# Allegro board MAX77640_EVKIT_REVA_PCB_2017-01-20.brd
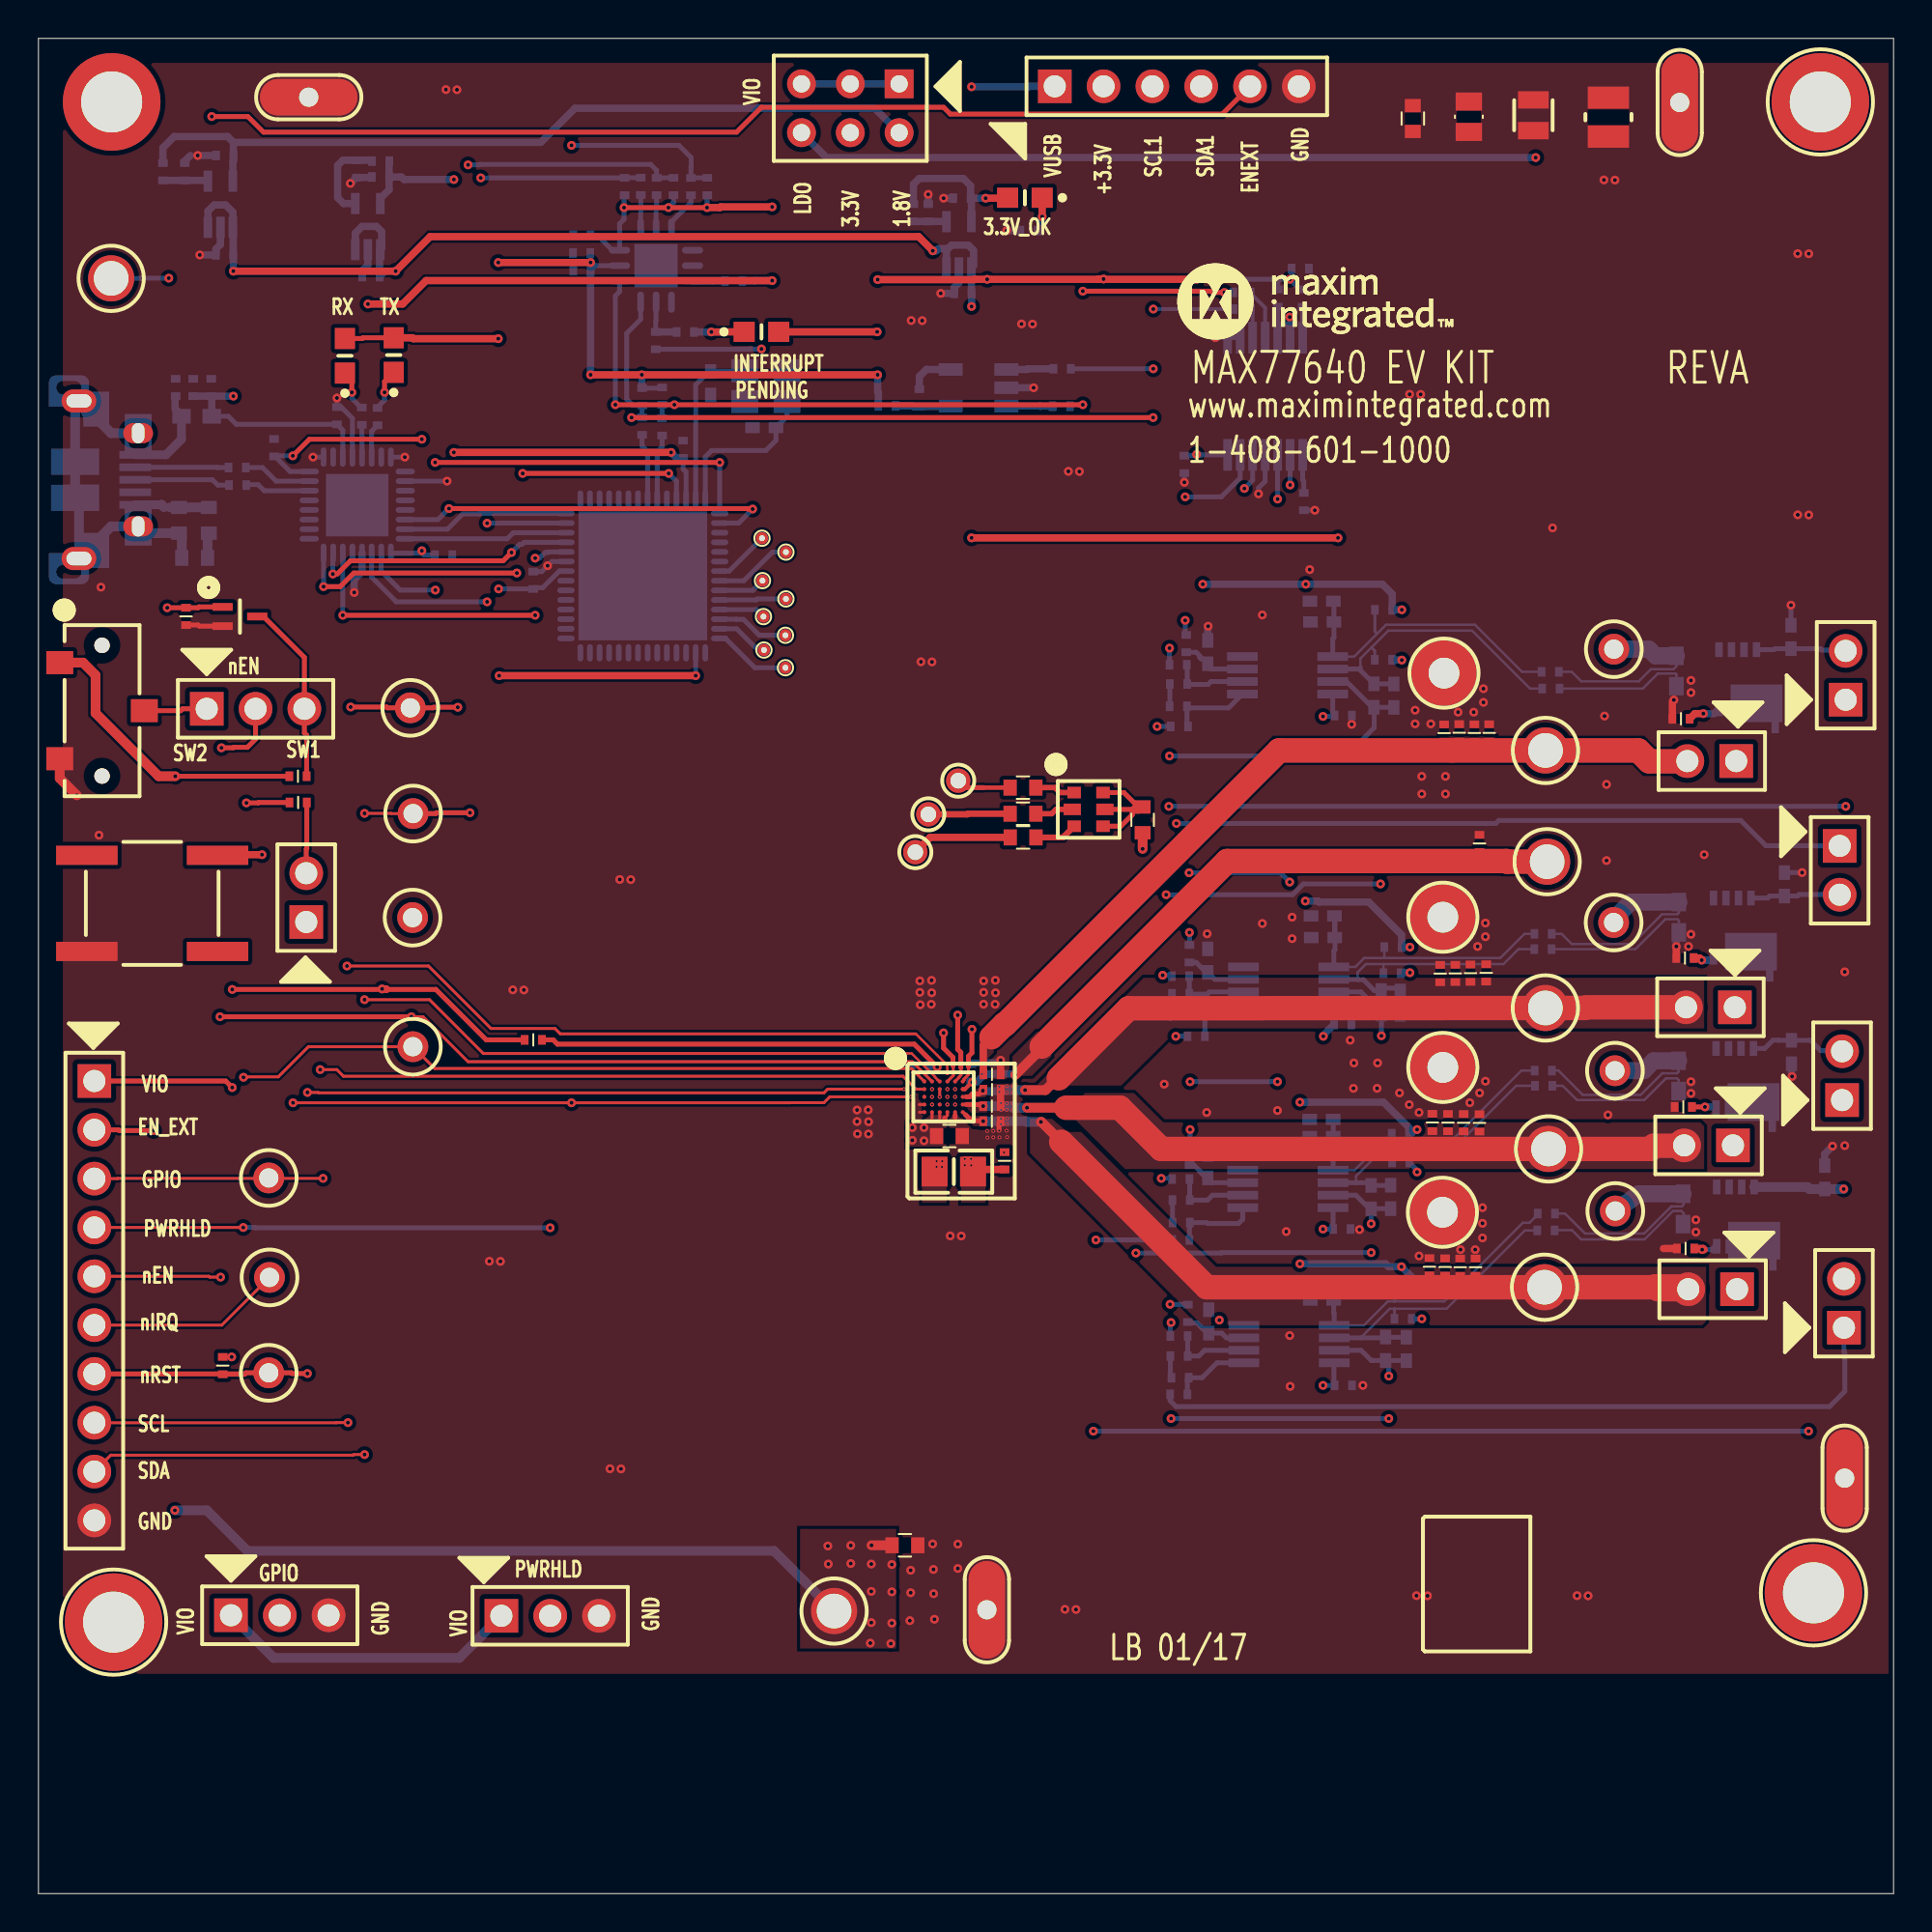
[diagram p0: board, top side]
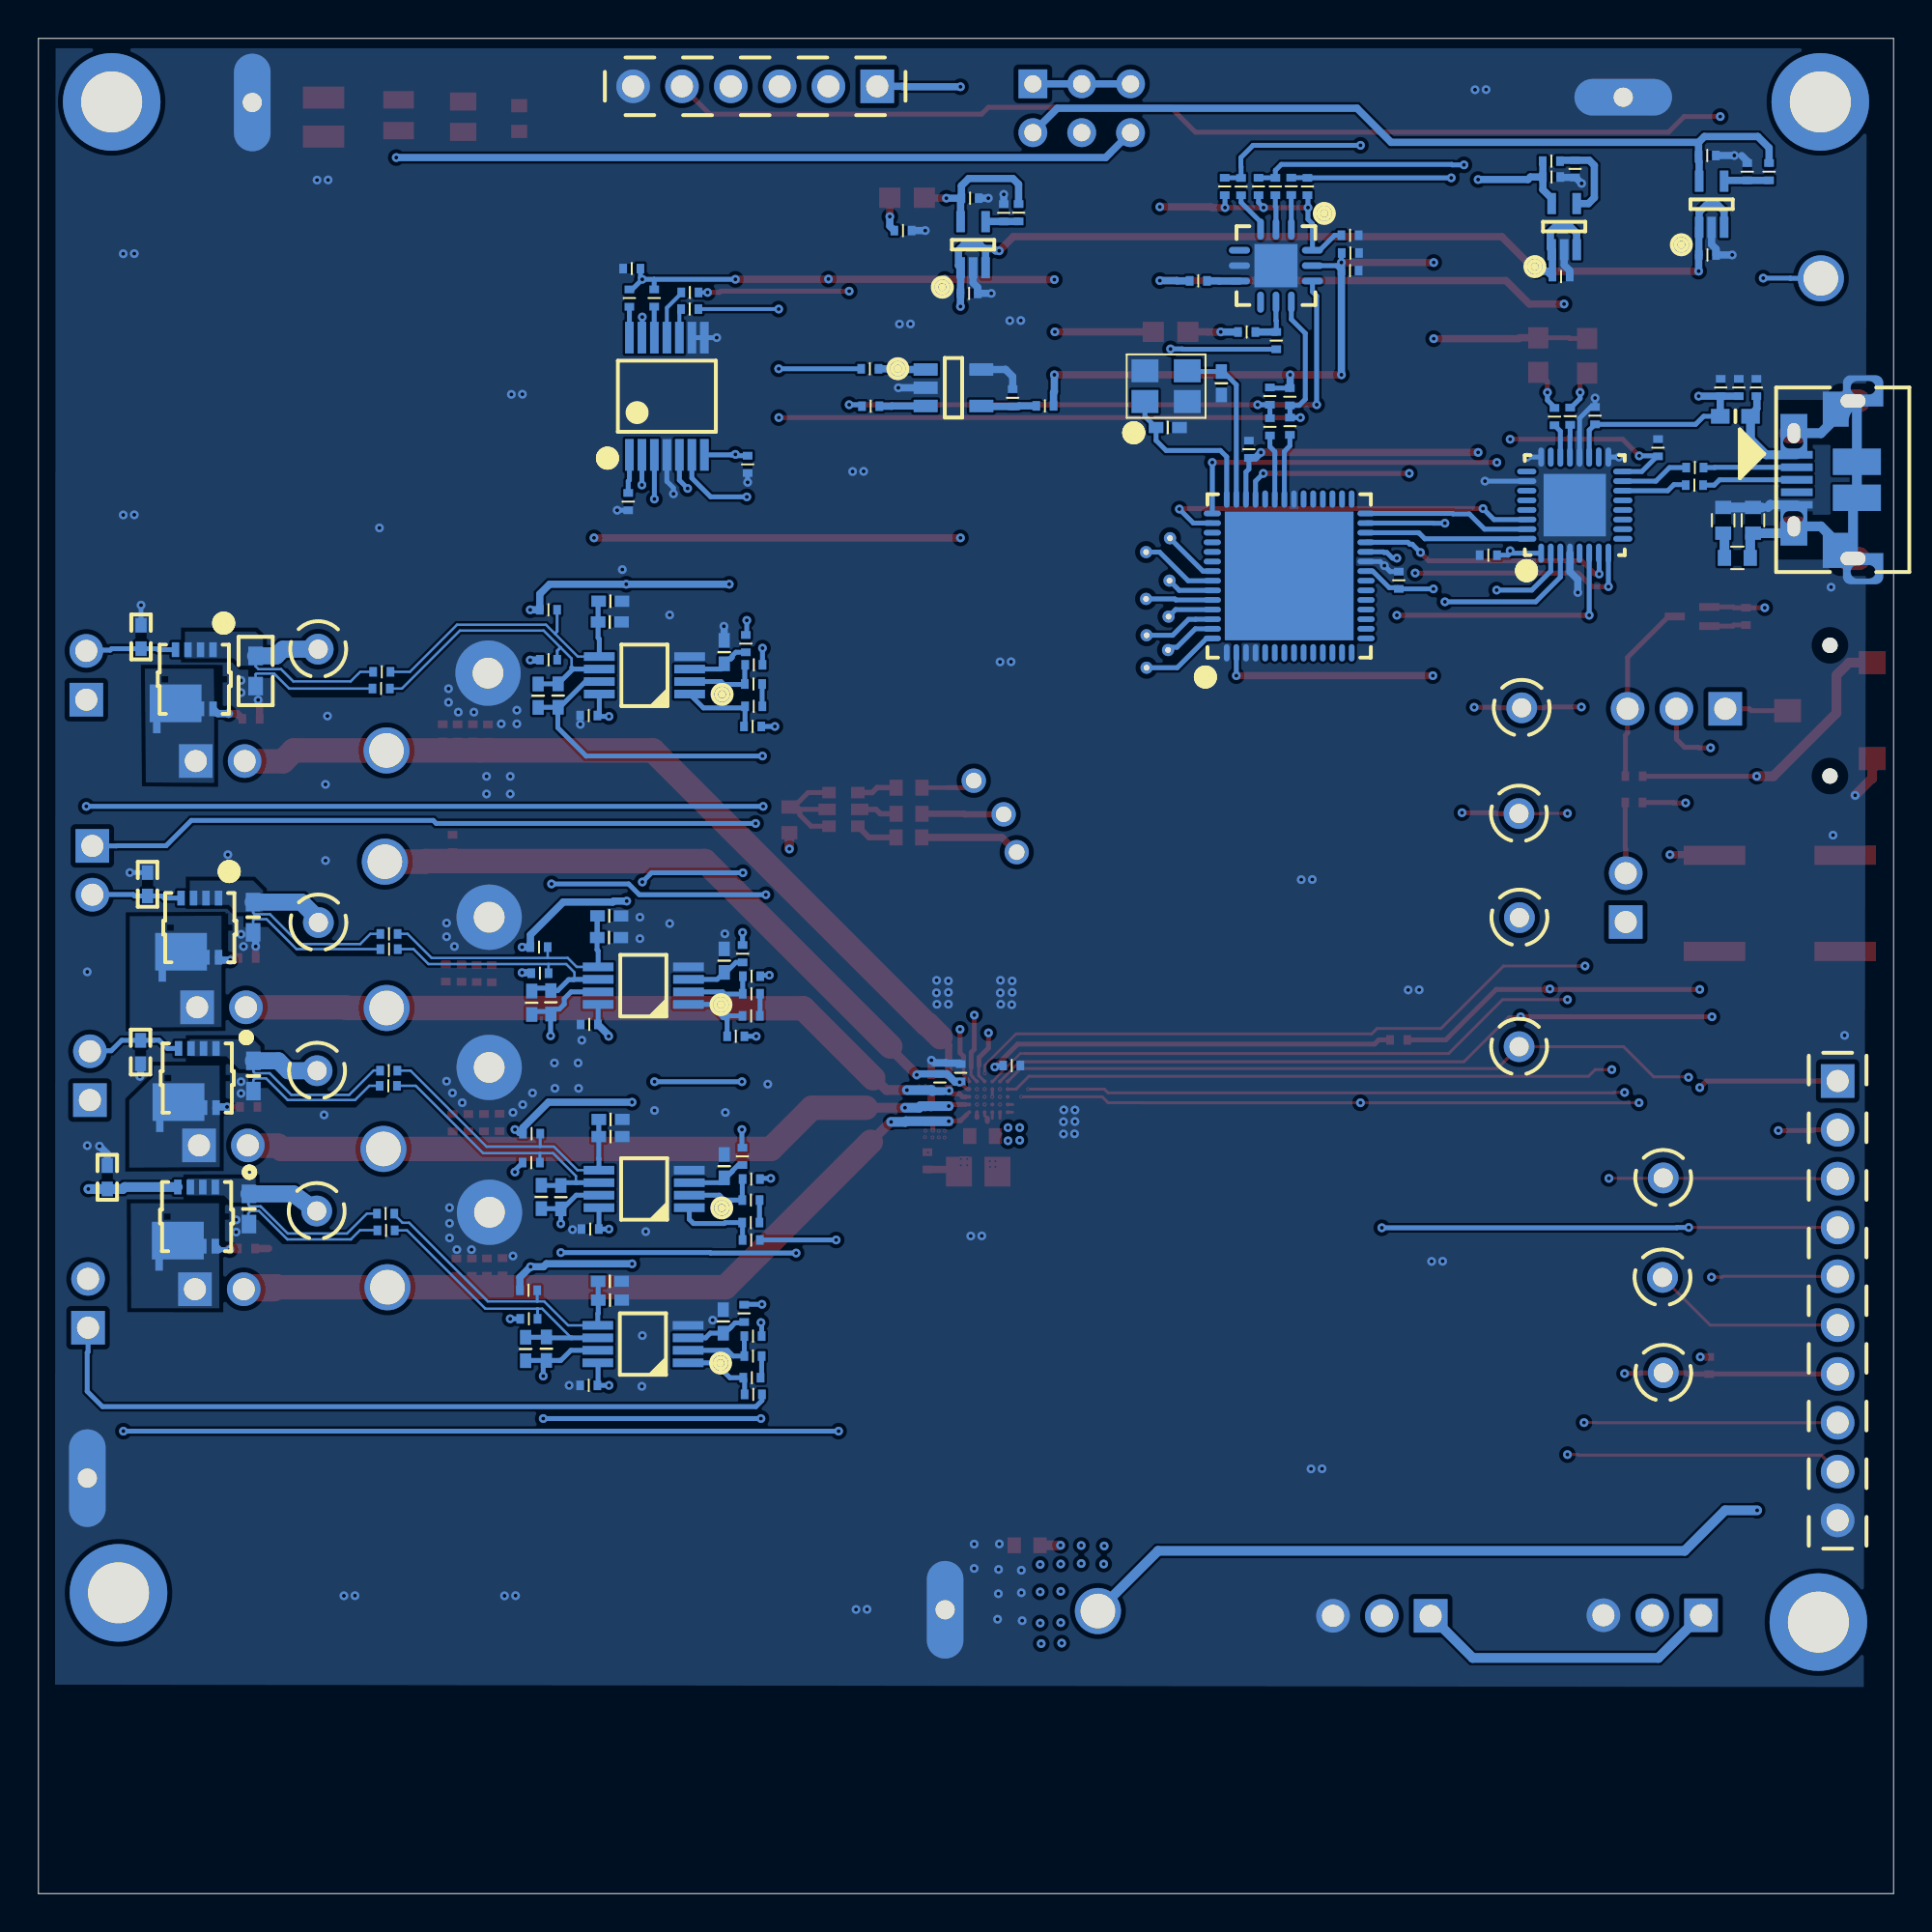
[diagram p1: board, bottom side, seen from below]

Outline 96.52 x 96.52 mm; copper layers: TOP, INTERNAL2, INTERNAL3, BOTTOM. Coordinates in mm from the lower left corner of the outline.
Outline path: 0,96.52 0,0 96.52,0 96.52,96.52 0,96.52

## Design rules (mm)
constraint set DEFAULT: min track width 0.102
net group NIRQ: nets NIRQ UNNAMED_4_EKRESSMD_I87_1
net group NIRQ1: nets NIRQ1 UNNAMED_4_EKRESSMD_I190_2
net group UNNAMED_4_10103592-0001LF_I2_2: nets UNNAMED_4_10103592-0001LF_I2_2 UNNAMED_4_EKRESSMD_I15_2
net group UNNAMED_4_10103592-0001LF_I2_3: nets UNNAMED_4_10103592-0001LF_I2_3 UNNAMED_4_EKRESSMD_I16_2
net group UNNAMED_4_10103592-0001LF_I2_SHIELD10: nets UNNAMED_4_10103592-0001LF_I2_SHIELD10 UNNAMED_4_EKCAPNP_I29_1
net group UNNAMED_4_EKRESSMD_I17_1: nets UNNAMED_4_EKRESSMD_I17_1 UNNAMED_4_EKRESSMD_I17_2
net group UNNAMED_4_EKRESSMD_I18_1: nets UNNAMED_4_EKRESSMD_I18_1 UNNAMED_4_EKRESSMD_I18_2
net group VUSB: nets UNNAMED_4_10103592-0001LF_I2_1 VUSB
net group SCL: nets SCL SDA UNNAMED_4_EKRESSMD_I153_1 UNNAMED_4_EKRESSMD_I154_1 UNNAMED_4_EKRESSMD_I171_2 VIO
net group SCL1: nets SCL1 UNNAMED_4_EKRESSMD_I109_1 UNNAMED_6_24AA02_I452_SCL
net group SDA1: nets SDA1 UNNAMED_4_EKRESSMD_I113_1 UNNAMED_6_24AA02_I452_SDA

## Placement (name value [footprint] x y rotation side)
C1  22UF  [CAPC1608X90L]  47.4 39.41 0 top
C2  0.01UF  [CAPC1005X50L]  75.33 47.9 270 top
C4  3300PF  [0402]  50.27 38.13 270 top
C5  10UF  [CAPC1005X50L]  49.61 42.62 180 top
C6  10UF  [CAPC1005X50L]  49.61 40.18 180 top
C8  10UF  [CAPC1005X50L]  49.61 40.97 180 top
C9  10UF  [CAPC1005X50L]  49.61 41.82 180 top
C12  1UF  [CAPC1005X50L]  45.88 43.08 0 bottom
C13  10UF  [CAPC1005X50L]  48.54 42.7 90 bottom
C14  0.1UF  [CAPC1005X50L]  45.83 77.82 270 bottom
C17  10UF  [CAPC1005X50L]  73.13 60.38 270 top
C18  OPEN  [CAPC1005X50L]  74.97 54.64 270 top
C19  OPEN  [CAPC1005X50L]  72.93 47.87 270 top
C20  10UF  [CAPC1005X50L]  72.53 40.12 270 top
C21  OPEN  [CAPC1005X50L]  73.72 47.88 270 top
C22  OPEN  [CAPC1005X50L]  73.34 40.11 270 top
C23  OPEN  [CAPC1005X50L]  73.92 60.39 270 top
C24  OPEN  [CAPC1005X50L]  72.37 32.61 270 top
C25  0.1UF  [CAPC1005X50L]  74.71 60.38 270 top
C26  OPEN  [CAPC1005X50L]  73.19 32.6 270 top
C27  0.1UF  [CAPC1005X50L]  74.51 47.89 270 top
C28  0.1UF  [CAPC1005X50L]  74.15 40.1 270 top
C29  0.1UF  [CAPC1005X50L]  73.97 32.59 270 top
C30  22UF  [CAPC1608X90L]  45.08 18.12 0 top
C31  0.01UF  [CAPC1005X50L]  74.97 40.1 270 top
C32  0.01UF  [CAPC1005X50L]  74.77 32.59 270 top
C33  0.01UF  [CAPC1005X50L]  75.48 60.39 270 top
C108  0.1UF  [CAPC1005X50L]  15.53 76.89 270 bottom
C110  1UF  [CAPC1005X50L]  9.68 85.26 0 bottom
C111  1UF  [CAPC1005X50L]  9.69 90.43 0 bottom
C112  1UF  [CAPC1005X50L]  17.3 84.13 0 bottom
C113  1UF  [CAPC1005X50L]  17.8 89.31 0 bottom
C114  0.47UF  [CAPC1608X90L]  8.86 71.45 90 bottom
C115  1UF  [CAPC1005X50L]  28.28 84.44 0 bottom
C118  1UF  [CAPC1005X50L]  48.1 83.26 0 bottom
C120  1UF  [CAPC1005X50L]  28.28 86.28 0 bottom
C150  0.1UF  [CAPC1005X50L]  25.74 68.33 90 bottom
C151  0.1UF  [CAPC1005X50L]  33.54 75.15 90 bottom
C152  15PF  [0402#2]  37.76 76.28 0 bottom
C153  15PF  [0402#2]  34.97 78.58 90 bottom
C154  4.7UF  [CAPC1005X50L]  8.05 78.36 270 bottom
C155  0.1UF  [CAPC1005X50L]  7.14 78.36 90 bottom
C156  0.1UF  [CAPC1005X50L]  12.26 75.23 270 bottom
C157  0.1UF  [CAPC1005X50L]  28.26 85.36 0 bottom
C158  1UF  [CAPC1005X50L]  48.05 88.21 0 bottom
C159  0.1UF  [CAPC1005X50L]  21.08 69.63 0 bottom
C200  4700PF  [0402#2]  60.84 48.54 270 bottom
C201  1000PF  [CAPC1005X50L]  59.43 46.82 180 bottom
C202  0.1UF  [CAPC1005X50L]  67.86 45.22 0 bottom
C203  18PF  [0402#2]  69.86 46.37 90 bottom
C204  18PF  [0402#2]  66.83 49.74 0 bottom
C206  1000PF  [CAPC1005X50L]  59.45 36.08 180 bottom
C207  0.1UF  [CAPC1005X50L]  67.81 34.57 0 bottom
C208  18PF  [0402#2]  66.76 39.38 0 bottom
C209  18PF  [0402#2]  70.35 36.25 90 bottom
C211  1000PF  [CAPC1005X50L]  59.34 27.97 180 bottom
C212  0.1UF  [CAPC1005X50L]  67.89 26.44 0 bottom
C213  18PF  [0402#2]  70.09 28.35 90 bottom
C214  18PF  [0402#2]  66.78 30.88 0 bottom
C216  1000PF  [CAPC1005X50L]  59.32 62.93 180 bottom
C217  0.1UF  [CAPC1005X50L]  67.89 61.29 0 bottom
C218  18PF  [0402#2]  66.79 66.16 0 bottom
C219  18PF  [0402#2]  69.48 62.33 90 bottom
C221  0.1UF  [CAPC1005X50L]  65.65 84.55 180 bottom
C222  0.1UF  [CAPC1005X50L]  59.62 74.36 90 bottom
C223  0.1UF  [CAPC1005X50L]  65.83 72.42 90 bottom
C239  1UF  [CAPC1005X50L]  85.67 48.67 0 top
C240  1UF  [CAPC1005X50L]  85.58 40.93 0 top
C241  1UF  [CAPC1005X50L]  85.7 33.56 0 top
C242  1UF  [CAPC1005X50L]  85.46 61.12 0 top
C248  4700PF  [0402#2]  60.84 37.85 270 bottom
C250  4700PF  [0402#2]  60.89 29.77 270 bottom
C251  4700PF  [0402#2]  60.84 64.59 270 bottom
D100  LTST-C190YKT  [LEDC1608X80M]  18.48 80.05 90 top
D101  LTST-C190YKT  [LEDC1608X80M]  15.94 80.01 90 top
D102  LTST-C190CKT  [LEDC1608X80M]  51.32 88.23 180 top
D103  LTST-C190CKT  [LEDC1608X80M]  37.62 81.25 0 top
DS1  19-337/R6GHBHC-A01/2T  [LED_R6GHBHC]  54.64 56.41 0 top
EN_EXT  N/A  [TP_C240H180]  3.78 84.04 0 top
FB100  220  [0603#2]  8.23 76.86 0 bottom
GND1  N/A  [TP_C340H160]  73.13 63.5 90 top
GND2  MAXIMPAD  [EVK_MAXIMPAD]  49.35 14.77 270 top
GND3  MAXIMPAD  [EVK_MAXIMPAD]  14.06 93.46 0 top
GND4  MAXIMPAD  [EVK_MAXIMPAD]  85.39 93.19 270 top
GND5  N/A  [TP_C340H160]  73.05 35.45 0 top
GND6  N/A  [TP_C340H160]  73.07 42.98 0 top
GND7  N/A  [TP_C340H160]  73.07 50.8 0 top
GND8  MAXIMPAD  [EVK_MAXIMPAD]  93.98 21.61 90 top
GPIO  N/A  [TP_180P120D460H]  11.98 37.23 0 top
INLDO  N/A  [TP_C240H180]  78.5 53.69 0 top
J2  PBC10SAAN  [SULLINS_PXC10SAAN]  2.91 42.28 270 top
J3  TSW-103-07-T-S  [SAMTEC_TSW-103-07-T-S]  10.02 14.48 0 top
J4  TSW-103-07-T-S  [SAMTEC_TSW-103-07-T-S]  24.09 14.45 0 top
J5  TSW-103-07-T-S  [SAMTEC_TSW-103-07-T-S]  8.76 61.64 0 top
J6  10103592-0001LF  [FCI_10103592-0001LF]  2.11 73.56 90 bottom
J8  TSW-102-07-T-S  [SAMTEC_TSW-102-07-X-S]  13.93 50.55 90 top
J100  PBC06SAAN  [SULLINS_PXC06SAAN]  52.88 94.03 0 top
J101  TSW-102-26-T-T  [SAMTEC_TSW-102-26-X-T]  44.78 94.16 270 top
J200  TSW-102-07-T-S  [SAMTEC_TSW-102-07-X-S]  93.72 54.51 270 top
J201  TSW-102-07-T-S  [SAMTEC_TSW-102-07-X-S]  88.26 46.11 180 top
J202  TSW-102-07-T-S  [SAMTEC_TSW-102-07-X-S]  93.84 41.28 90 top
J203  TSW-102-07-T-S  [SAMTEC_TSW-102-07-X-S]  88.16 38.93 180 top
J204  TSW-102-07-T-S  [SAMTEC_TSW-102-07-X-S]  93.94 29.44 90 top
J205  TSW-102-07-T-S  [SAMTEC_TSW-102-07-X-S]  88.38 31.44 180 top
J206  TSW-102-07-T-S  [SAMTEC_TSW-102-07-X-S]  94.03 62.12 90 top
J207  TSW-102-07-T-S  [SAMTEC_TSW-102-07-X-S]  88.33 58.92 180 top
L1  1.5UH  [0805]  47.62 37.56 180 top
L2  0.47UH  [0603]  71.51 92.35 90 top
L3  2.2UH  [0805#2]  74.42 92.45 90 top
L4  2.2UH  [IND_2016]  77.78 92.53 90 top
L5  2.2UH  [IND_2520]  81.69 92.43 90 top
LDO  N/A  [TP_C240H180]  78.41 59.48 0 top
LED0  NA  [TP_C127H81]  47.86 57.9 0 top
LED1  NA  [TP_C127H81]  46.3 56.15 0 top
LED2  NA  [TP_C127H81]  45.62 54.18 0 top
NEN  N/A  [TP_180P120D460H]  19.47 50.78 0 top
NIRQ  N/A  [TP_180P120D460H]  12.02 32.06 0 top
NOREF  -  [unnamed]  3.91 14.12 0 top
NOREF#2  -  [unnamed]  3.81 93.22 0 top
NOREF#3  -  [unnamed]  92.35 15.65 0 top
NOREF#4  -  [#2]  61.29 82.75 0 top
NOREF#5  -  [#2]  -23.98 89.1 0 top
NOREF#6  -  [#2]  49.43 150.22 0 top
NOREF#7  -  [#2]  12.75 1.73 0 top
NOREF#8  -  [unnamed]  92.71 93.22 0 top
NOREF#9  -  [#2]  108.1 89.1 0 top
NOREF#10  -  [#2]  108.1 -9.96 0 top
NRST  N/A  [TP_180P120D460H]  11.98 27.09 0 top
PO0  N/A  [TP_C25H12]  37.65 70.52 90 top
PO1  N/A  [TP_C25H12]  38.89 69.8 90 top
PO2  N/A  [TP_C25H12]  37.67 68.31 90 top
PO3  N/A  [TP_C25H12]  38.89 67.36 90 top
PO4  N/A  [TP_C25H12]  37.72 66.44 90 top
PO5  N/A  [TP_C25H12]  38.86 65.47 90 top
PO6  N/A  [TP_C25H12]  37.75 64.7 90 top
PO7  N/A  [TP_C25H12]  38.86 63.78 90 top
PWRHLD  N/A  [TP_180P120D460H]  19.48 44.06 0 top
Q1  FDY300NZ  [SOT50P160X90-3M]  10.48 66.44 0 top
Q200  IRFHM8337TRPBF  [TRAN_IRF_PQFN8_SINGLE_B]  88.13 50.26 270 bottom
Q201  IRFHM8337TRPBF  [TRAN_IRF_PQFN8_SINGLE_B]  88.26 42.43 270 bottom
Q202  IRFHM8337TRPBF  [TRAN_IRF_PQFN8_SINGLE_B]  88.29 35.22 270 bottom
Q203  IRFHM8337TRPBF  [TRAN_IRF_PQFN8_SINGLE_B]  88.41 63.18 270 bottom
R1  100K  [RESC1005X50L]  7.61 89.59 90 bottom
R2  10K  [0402]  13.5 58.13 180 top
R3  100K  [RESC1005X50L]  7.68 66.45 270 top
R6  0  [RESC1608X90L]  51.23 54.95 180 top
R7  0  [RESC1608X90L]  51.22 57.54 180 top
R8  0  [RESC1608X90L]  51.22 56.18 180 top
R9  0  [RESC1608X90L]  57.45 55.86 90 top
R10  10K  [0402]  9.59 27.47 90 top
R11  0  [RESC1005X50L]  49.62 42.2 270 bottom
R14  100K  [RESC1005X50L]  34.8 88.82 270 bottom
R16  150  [0402]  13.51 56.77 0 top
R17  0  [RESC1005X50L]  25.75 44.42 180 top
R100  4.7K  [RESC1005X50L]  32.45 77.91 90 bottom
R103  22  [RESC1005X50L]  10.36 73.28 0 bottom
R107  2.2K  [RESC1005X50L]  33.04 88.82 90 bottom
R108  2.2K  [RESC1005X50L]  30.5 88.82 90 bottom
R109  100  [RESC1005X50L]  16.83 76.87 90 bottom
R110  470  [0402]  51.54 86.52 180 bottom
R111  100  [RESC1005X50L]  17.64 76.84 90 bottom
R115  100K  [RESC1005X50L]  8.99 78.36 90 bottom
R118  4.7K  [RESC1005X50L]  31.41 77.88 90 bottom
R122  1M  [RESC1608X90L]  7.32 71.45 90 bottom
R123  22  [RESC1005X50L]  10.34 74.19 0 bottom
R135  0  [RESC1005X50L]  31.34 88.83 90 bottom
R136  0  [RESC1005X50L]  32.16 88.82 90 bottom
R142  0  [RESC1608X90L]  8.13 69.49 0 bottom
R143  0  [RESC1005X50L]  36.17 83.91 180 bottom
R148  0  [RESC1005X50L]  32.45 76.31 90 bottom
R150  22  [RESC1005X50L]  33.95 88.81 90 bottom
R152  0  [RESC1005X50L]  32.12 80.8 90 bottom
R155  0  [RESC1005X50L]  31.41 76.34 90 bottom
R156  105K  [0402]  17.81 90.14 180 bottom
R157  100K  [RESC1005X50L]  16.57 89.73 270 bottom
R158  169K  [0402]  45.53 87.45 270 bottom
R159  100K  [RESC1005X50L]  46.29 87.45 90 bottom
R160  47.5K  [0402]  6.48 89.59 270 bottom
R161  470  [0402]  33.66 81.25 180 bottom
R162  0  [RESC1005X50L]  53.26 79.33 180 bottom
R163  0  [RESC1005X50L]  44.15 77.4 180 bottom
R164  0  [RESC1005X50L]  53.22 77.39 0 bottom
R201  100  [0402]  59.44 45.67 0 bottom
R202  680  [0402]  59.42 47.73 180 bottom
R203  20K  [0402]  59.88 48.9 270 bottom
R204  0  [RESC1005X50L]  60.24 44.6 180 bottom
R205  4.99K  [0402#2]  70.85 46.35 90 bottom
R206  4.99K  [0402#2]  66.82 50.86 0 bottom
R207  1K  [RESC1005X50L]  78.28 49.93 0 bottom
R208  1K  [RESC1005X50L]  78.28 49.14 0 bottom
R210  1M  [0402#2]  90.84 52.51 270 bottom
R211  1  [0603#2]  85.35 50.8 270 bottom
R214  100K  [RESC1005X50L]  65.78 83.01 90 bottom
R222  100  [0402]  59.46 34.91 0 bottom
R223  680  [0402]  59.43 37.17 180 bottom
R224  20K  [0402]  59.89 38.36 270 bottom
R225  0  [RESC1005X50L]  59.44 34.01 180 bottom
R226  4.99K  [0402#2]  66.75 40.28 0 bottom
R228  4.99K  [0402#2]  69.34 36.23 90 bottom
R229  1K  [RESC1005X50L]  78.3 42.82 0 bottom
R230  1K  [RESC1005X50L]  78.32 42.03 0 bottom
R231  1M  [0402#2]  91.21 43.78 90 bottom
R233  1  [0603#2]  85.34 42.54 270 bottom
R235  100  [0402]  59.4 26.84 0 bottom
R236  680  [0402]  59.34 29 180 bottom
R237  20K  [0402]  59.8 30.19 270 bottom
R238  0  [RESC1005X50L]  59.33 25.97 180 bottom
R239  4.99K  [0402#2]  71.17 28.33 90 bottom
R240  4.99K  [0402#2]  66.79 31.86 0 bottom
R242  1K  [RESC1005X50L]  78.46 35.38 0 bottom
R243  1K  [RESC1005X50L]  78.44 34.5 0 bottom
R244  1M  [0402#2]  92.94 37.27 270 bottom
R245  1  [0603#2]  85.57 35.62 270 bottom
R248  100  [0402]  59.31 61.77 0 bottom
R249  680  [0402]  59.3 63.93 180 bottom
R250  20K  [0402]  59.72 65.03 270 bottom
R251  0  [RESC1005X50L]  59.36 60.72 180 bottom
R252  4.99K  [0402#2]  66.76 67.24 0 bottom
R253  4.99K  [0402#2]  70.52 62.32 90 bottom
R254  1K  [RESC1005X50L]  78.66 63.57 0 bottom
R255  1K  [RESC1005X50L]  78.69 62.7 0 bottom
R257  1M  [0402#2]  91.18 65.38 270 bottom
R258  1  [0603#2]  85.22 63.61 270 bottom
R283  100K  [RESC1005X50L]  64.48 83.01 270 bottom
R293  470K  [0402]  70.47 49.24 0 bottom
R294  649K  [0402]  70.43 47.89 180 bottom
R295  470K  [0402]  70.86 39.54 0 bottom
R296  649K  [0402]  70.88 38.03 180 bottom
R297  470K  [0402]  71.02 31.39 0 bottom
R298  649K  [0402]  71 29.9 180 bottom
R299  470K  [0402]  69.98 66.79 0 bottom
R300  649K  [0402]  69.98 64.19 180 bottom
R305  0  [RESC1005X50L]  62.63 82.44 0 bottom
R306  0  [RESC1005X50L]  62.62 83.3 0 bottom
SBB0  N/A  [TP_C240H180]  78.4 46.08 0 top
SBB1  N/A  [TP_C240H180]  78.57 38.74 0 top
SBB2  N/A  [TP_C240H180]  78.36 31.55 0 top
SCL  N/A  [TP_180P120D460H]  19.35 61.69 0 top
SDA  N/A  [TP_180P120D460H]  19.49 56.19 0 top
SW1  EVQ-Q2K03W  [SW_EVQ-Q2X03W]  5.92 51.52 180 top
SW2  CL-SB-12B-11  [SW_CL-SB-12B-1X]  3.31 61.54 0 top
U1  MAX77640  [BGA30C40P6X5_275X215X69M]  47.09 41.45 0 top
U100  MAXQ2000-RBX+  [QFN50P800X800X80-57M]  31.45 68.55 90 bottom
U101  FT232RQ  [QFN50P500X500X100-33V2M]  16.59 72.24 90 bottom
U102  MAX8512EXK  [SOT65P210X110-5M]  47.89 85.79 90 bottom
U103  MAX8512EXK  [SOT65P210X110-5M]  9.47 87.89 90 bottom
U104  MAX8512EXK  [SOT65P210X110-5M]  17.14 86.73 90 bottom
U107  MAX3395EETC  [QFN80P400X400X80-13M]  32.13 84.7 270 bottom
U108  24AA02T-I/OT  [SOT95P280X145-5M]  48.91 78.35 180 bottom
U200  MAX44251AUA+  [SOP65P490X110-8M]  65.05 47.24 0 bottom
U201  MAX44251AUA+  [SOP65P490X110-8M]  65.01 36.66 0 bottom
U202  MAX44251AUA+  [SOP65P490X110-8M]  65.07 28.59 0 bottom
U203  MAX44251AUA+  [SOP65P490X110-8M]  64.99 63.38 0 bottom
U205  MAX5815AAUD+  [SOP65P640X120-14M]  63.82 77.9 90 bottom
VIL_LDO  N/A  [TP_180P120D460H]  81.97 64.74 0 top
VIL_SBB0  N/A  [TP_180P120D460H]  81.95 50.52 0 top
VIL_SBB1  N/A  [TP_180P120D460H]  82.02 42.81 0 top
VIL_SBB2  N/A  [TP_180P120D460H]  82.04 35.51 0 top
VSYS  N/A  [TP_C240H180]  41.4 14.7 0 top
Y101  16MHZ  [XTAL320X250X070M]  37.85 78.43 180 bottom

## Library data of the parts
C1 C30 = EK_CAP_NP: part number: EK_CAP_NP_0603_FF-CAPC1608X90L,22UF,20-0022U-A48
C2 C31-C33 = EK_CAP_NP: part number: EK_CAP_NP_0402_FF-CAPC1005X50L,0.01UF,20-00U01-B8
C4 = CAP_NP: alternate symbols: 0402_NOSILK,CAPC1005X50L; part number: CAP_NP_0402CAP-0402,3300PF,20-3300P-04
C5 C6 C8 C9 C13 C17 C20 = EK_CAP_NP: part number: EK_CAP_NP_0402_FF-CAPC1005X50L,10UF,20-0010U-B65
C12 C110-C113 C115 C118 C120 C158 C239-C242 = EK_CAP_NP: part number: EK_CAP_NP_0402_FF-CAPC1005X50L,1UF,20-0001U-B65
C14 C156 C157 = EK_CAP_NP: part number: EK_CAP_NP_0402_FF-CAPC1005X50L,0.1UF,20-000U1-12; signal model: DEFAULT_CAPACITOR_100000pF_2_1
C18 C19 C21-C24 C26 = EK_CAP_NP: alternate symbols: 0402,0402_NOSILK; part number: EK_CAP_NP_0402_FF-CAPC1005X50L,OPEN,N/A
C25 C27-C29 = EK_CAP_NP: part number: EK_CAP_NP_0402_FF-CAPC1005X50L,0.1UF,20-000U1-33
C108 C150 C151 C155 C159 C202 C207 C212 C217 C221-C223 = EK_CAP_NP: part number: EK_CAP_NP_0402_FF-CAPC1005X50L,0.1UF,20-000U1-12
C114 = EK_CAP_NP: part number: EK_CAP_NP_0603_FF-CAPC1608X90L,0.47UF,20-00U47-16; signal model: DEFAULT_CAPACITOR_470000pF_2_1
C152 C153 = CAP_NP: alternate symbols: 0402_NOSILK,CAPC1005X50L; part number: CAP_NP_0402CAP-0402,15PF,20-0015P-F3
C154 = EK_CAP_NP: part number: EK_CAP_NP_0402_FF-CAPC1005X50L,4.7UF,20-004U7-33A; signal model: DEFAULT_CAPACITOR_4.7e+06pF_2_1
C200 C248 C250 C251 = CAP_NP: alternate symbols: (0402_NOSILK); part number: CAP_NP_0402CAP-0402,4700PF,20-4700P-A0Z
C201 C206 C211 C216 = EK_CAP_NP: part number: EK_CAP_NP_0402_FF-CAPC1005X50L,1000PF,20-1000P-E7
C203 C204 C208 C209 C213 C214 C218 C219 = CAP_NP: alternate symbols: 0402_NOSILK,CAPC1005X50L; part number: CAP_NP_0402CAP-0402,18PF,20-0018P-27
D100 D101 = LED: part number: LED_LEDC1608X80M-LEDC1608X80M,LTST-C190YKT,30-LTSTC190YKT-00
D102 D103 = LED: part number: LED_LEDC1608X80M-LEDC1608X80M,LTST-C190CKT,30-LTSTC190CKT-00
DS1 = LED_6P: part number: LED_6P_R6GHBHC-LED_R6GHBHC,19-337/R6GHBHC-A01/2T,30-19337R6GHBHCA012T-00
EN_EXT INLDO LDO SBB0-SBB2 VSYS = TP: alternate symbols: TP_C340H160L; part number: TP_TP-TP_C240H180,N/A,02-TPMINI5010-00
FB100 = INDUCT: alternate symbols: (0603_NOSILK); part number: INDUCT_0603-0603,220,50-00220-SM12A; signal model: DEFAULT_INDUCTOR_220.000000nH_1_2
GND1 GND5-GND7 = TP: alternate symbols: TP_C340H160L; part number: TP_TP-TP_C340H160,N/A,02-TPMINI5011-00
GND2-GND4 GND8 = EVK_MAXIMPAD: alternate symbols: EVK_MAXIMPAD_ALT; part number: EVK_MAXIMPAD_MISC-EVK_MAXIMPAD,MAXIMPAD,01-9020BUSS20AWG-00
GPIO NEN NIRQ NRST PWRHLD SCL SDA = TP: part number: TP_TP-TP_180P120D460H,N/A,02-TPMINI5002-00
J2 = HEADER_10P: part number: HEADER_10P_TH-SULLINS_PXC10SAAN,PBC10SAAN,01-PBC10SAAN10P-21
J3-J5 = HEADER_3P: part number: HEADER_3P_SIP-SAMTEC_TSW-103-07-T-S,TSW-103-07-T-S,01-TSW10307TS3P-17
J6 = 10103592-0001LF: part number: 10103592-0001LF_SMT-FCI_10103592-0001LF,10103592-0001LF,01-101035920001LF5P-26
J8 J200-J207 = HEADER_2P: part number: HEADER_2P_TH-SAMTEC_TSW-102-07-X-S,TSW-102-07-T-S,01-TSW10207TS2P-17
J100 = HEADER_6P: part number: HEADER_6P_TH-SULLINS_PXC06SAAN,PBC06SAAN,01-PBC06SAAN6P-21
J101 = HEADER_2P_X_3R: part number: HEADER_2P_X_3R_TH-SAMTEC_TSW-102-26-X-T,TSW-102-26-T-T,01-TSW10226TT6P-17
L1 = EVKIT_INDUCT: alternate symbols: INDC2012X145L; part number: EVKIT_INDUCT_IND_0805-0805,1.5UH,50-001U5-0LP
L2 = INDUCT: alternate symbols: 0603_NOSILK,INDC1608X90L; part number: INDUCT_0603-0603,0.47UH,50-00U47-0DK
L3 = EVKIT_INDUCT: alternate symbols: INDC2012X145L; part number: EVKIT_INDUCT_IND_0805-0805,2.2UH,50-002U2-0LM
L4 = EVKIT_INDUCT: alternate symbols: INDC2016X100L; part number: EVKIT_INDUCT_IND_0806-IND_2016,2.2UH,50-002U2-0LO
L5 = EVKIT_INDUCT: alternate symbols: INDC2520X120L; part number: EVKIT_INDUCT_2520-IND_2520,2.2UH,50-002U2-0LN
LED0-LED2 = TP: part number: TP_TP-TP_C127H81,NA,NA
PO0-PO7 = TP: part number: TP_TP-TP_C25H12,N/A,N/A
Q1 = TRAN_NCH_3P: part number: TRAN_NCH_3P_SC89_TRENCH-SOT50P160X90-3M,FDY300NZ,90-FDY300NZ-28
Q200-Q203 = TRAN_NCH_8P: part number: TRAN_NCH_8P_PQFN8-TRAN_IRF_PQFN8_SINGLE_B,IRFHM8337TRPBF,90-IRFHM8337-10
R1 R3 R14 R157 R159 R214 R283 = EK_RES_SMD: part number: EK_RES_SMD_0402_FF-RESC1005X50L,100K,80-0100K-23
R2 R10 = RES: alternate symbols: 0402_NOSILK,RESC1005X50L,RES0402-NOT_FOR_TEST; part number: RES_0402RES-0402,10K,80-0010K-23
R6-R9 = EK_RES_SMD: part number: EK_RES_SMD_0603_FF-RESC1608X90L,0,80-0000R-27
R11 R17 R204 R225 R238 R251 R305 R306 = EK_RES_SMD: part number: EK_RES_SMD_0402_FF-RESC1005X50L,0,80-0000R-26
R16 = RES: alternate symbols: (0402_NOSILK,RESC1005X50L); part number: RES_0402RES-0402,150,80-0150R-23
R100 R118 = EK_RES_SMD: part number: EK_RES_SMD_0402_FF-RESC1005X50L,4.7K,80-004K7-23; signal model: DEFAULT_RESISTOR_4700OHM_2_1
R103 R123 = EK_RES_SMD: part number: EK_RES_SMD_0402_FF-RESC1005X50L,22,80-0022R-23; signal model: DEFAULT_RESISTOR_22.000000OHM_1_2
R107 R108 = EK_RES_SMD: part number: EK_RES_SMD_0402_FF-RESC1005X50L,2.2K,80-002K2-23; signal model: DEFAULT_RESISTOR_470.000000OHM_1_2
R109 R111 = EK_RES_SMD: part number: EK_RES_SMD_0402_FF-RESC1005X50L,100,80-0100R-23; signal model: DEFAULT_RESISTOR_100.000000OHM_2_1
R110 R161 = RES: alternate symbols: (0402_NOSILK,RESC1005X50L); part number: RES_0402RES-0402,470,80-0470R-23
R115 = EK_RES_SMD: part number: EK_RES_SMD_0402_FF-RESC1005X50L,100K,80-0100K-23; signal model: DEFAULT_RESISTOR_100000OHM_1_2
R122 = EK_RES_SMD: part number: EK_RES_SMD_0603_FF-RESC1608X90L,1M,80-0001M-19; signal model: DEFAULT_RESISTOR_0.001OHM_2_1
R135 R136 R148 R152 R155 R162-R164 = EK_RES_SMD: part number: EK_RES_SMD_0402_FF-RESC1005X50L,0,80-0000R-26; signal model: DEFAULT_RESISTOR_22.000000OHM_2_1
R142 = EK_RES_SMD: part number: EK_RES_SMD_0603_FF-RESC1608X90L,0,80-0000R-27; signal model: DEFAULT_RESISTOR_0.001OHM_2_1
R143 = EK_RES_SMD: part number: EK_RES_SMD_0402_FF-RESC1005X50L,0,80-0000R-26; signal model: DEFAULT_RESISTOR_0.001OHM_1_2
R150 = EK_RES_SMD: part number: EK_RES_SMD_0402_FF-RESC1005X50L,22,80-0022R-23; signal model: DEFAULT_RESISTOR_22.000000OHM_2_1
R156 = RES: alternate symbols: (0402_NOSILK,RESC1005X50L); part number: RES_0402RES-0402,105K,80-0105K-18
R158 = RES: alternate symbols: (0402_NOSILK,RESC1005X50L); part number: RES_0402RES-0402,169K,80-0169K-23
R160 = RES: alternate symbols: (0402_NOSILK,RESC1005X50L); part number: RES_0402RES-0402,47.5K,80-047K5-23
R201 R222 R235 R248 = RES: alternate symbols: 0402_NOSILK,RESC1005X50L,RES0402-NOT_FOR_TEST; part number: RES_0402RES-0402,100,80-0100R-23
R202 R223 R236 R249 = RES: alternate symbols: (0402_NOSILK,RESC1005X50L); part number: RES_0402RES-0402,680,80-0680R-23
R203 R224 R237 R250 = RES: alternate symbols: (0402_NOSILK,RESC1005X50L); part number: RES_0402RES-0402,20K,80-0020K-23
R205 R206 R226 R228 R239 R240 R252 R253 = RES: alternate symbols: (0402_NOSILK,RESC1005X50L); part number: RES_0402RES-0402,4.99K,80-04K99-23
R207 R208 R229 R230 R242 R243 R254 R255 = EK_RES_SMD: part number: EK_RES_SMD_0402_FF-RESC1005X50L,1K,80-0001K-23
R210 R231 R244 R257 = RES: alternate symbols: (0402_NOSILK,RESC1005X50L); part number: RES_0402RES-0402,1M,80-0001M-23
R211 R233 R245 R258 = RES: alternate symbols: (0603_NOSILK); part number: RES_0603RES-0603,1,80-0001R-24
R293 R295 R297 R299 = RES: alternate symbols: (0402_NOSILK,RESC1005X50L); part number: RES_0402RES-0402,470K,80-0470K-23
R294 R296 R298 R300 = RES: alternate symbols: 0402_NOSILK,RESC1005X50L; part number: RES_0402RES-0402,649K,80-0649K-AA18
SW1 = EVQ-Q2XXXX: part number: EVQ-Q2XXXX_SMT-SW_EVQ-Q2X03W,EVQ-Q2K03W,11-EVQQ2K03W-00
SW2 = CL-SB-12B-1X: part number: CL-SB-12B-1X_SMD-SW_CL-SB-12B-1X,CL-SB-12B-11,11-CLSB12B11-00
U1 = EK_MAX77640: alternate symbols: BGA30C40P6X5_275X215X69L; part number: EK_MAX77640_WLP30-BGA30C40P6X5_275X215X69M,MAX77640,N/A
U100 = MAXQ2000: part number: MAXQ2000_TQFN56-EP-QFN50P800X800X80-57M,MAXQ2000-RBX+,10-MAXQ2000RBX-T
U101 = FT232RQ: part number: FT232RQ_QFN32-EP-QFN50P500X500X100-33V2M,FT232RQ,10-FT232RQ-G
U102-U104 = MAX8512: part number: MAX8512_SC70-SOT65P210X110-5M,MAX8512EXK,10-MAX8512EXK-X
U107 = MAX3395E: part number: MAX3395E_TQFN-QFN80P400X400X80-13M,MAX3395EETC,10-MAX3395EETC-T
U108 = 24AA02: part number: 24AA02_SOT23-5-SOT95P280X145-5M,24AA02T-I/OT,10-24AA02TIOT-U
U200-U203 = MAX44251: part number: MAX44251_SPLIT_UMAX8-SOP65P490X110-8M,MAX44251AUA+,10-MAX44251AUA-U
U205 = MAX5815: part number: MAX5815_TSSOP14-SOP65P640X120-14M,MAX5815AAUD+,10-MAX5815AAUD-U
VIL_LDO VIL_SBB0-VIL_SBB2 = TP: part number: TP_TP-TP_180P120D460H,N/A,02-TPMINI5000-00
Y101 = XTAL: part number: XTAL_XTAL320X250X070M-XTAL320X250X070M,16MHZ,60-0016M-26A

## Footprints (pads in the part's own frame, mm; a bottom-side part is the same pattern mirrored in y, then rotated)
0402
  rect 0.4x0.5 smd: 1(-0.45,0) 2(0.45,0)
0402#2
  rect 0.762x0.584 smd: 1(-0.61,0) 2(0.61,0)
0603
  rect 0.69x0.83 smd: 1(-0.67,0) 2(0.67,0)
0603#2
  rect 0.965x0.762 smd: 1(-0.787,0) 2(0.787,0)
0805
  rect 1.35x1.55 smd: 1(-1,0) 2(1,0)
0805#2
  rect 0.94x1.37 smd: 1(-0.79,0) 2(0.79,0)
BGA30C40P6X5_275X215X69M
  round 0.21 smd: A1(-1,0.8) A2(-0.6,0.8) A3(-0.2,0.8) A4(0.2,0.8) A5(0.6,0.8) A6(1,0.8) B1(-1,0.4) B2(-0.6,0.4) B3(-0.2,0.4) B4(0.2,0.4) B5(0.6,0.4) B6(1,0.4) C1(-1,0) C2(-0.6,0) C3(-0.2,0) C4(0.2,0) C5(0.6,0) C6(1,0) D1(-1,-0.4) D2(-0.6,-0.4) D3(-0.2,-0.4) D4(0.2,-0.4) D5(0.6,-0.4) D6(1,-0.4) E1(-1,-0.8) E2(-0.6,-0.8) E3(-0.2,-0.8) E4(0.2,-0.8) E5(0.6,-0.8) E6(1,-0.8)
CAPC1005X50L
  rect 0.4x0.5 smd: 1(-0.45,0) 2(0.45,0)
CAPC1608X90L
  rect 0.69x0.83 smd: 1(-0.67,0) 2(0.67,0)
EVK_MAXIMPAD
  oval 5.08x1.905 hole 1: 1(0,0)
FCI_10103592-0001LF
  rect 0.4x1.65 smd: 1(1.3,2.925) 2(0.65,2.925) 3(0,2.925) 4(-0.65,2.925) 5(-1.3,2.925)
  oval 1.2x1.8 hole 0.7x1.3: 6(-4.1,0) 9(4.1,0)
  oval 1.05x1.55 hole 1.05x0.65: 7(-2.425,3.08) 8(2.425,3.08)
  rect 1.375x2.5 smd: 10(0.938,-0.2) 11(-0.938,-0.2)
IND_2016
  rect 0.9x1.6 smd: 1(-0.8,0) 2(0.8,0)
IND_2520
  rect 1.15x2.15 smd: 1(-1.015,0) 2(1.015,0)
LED_R6GHBHC
  rect 0.7x0.6 smd: 1(-0.75,0.875) 3(-0.75,-0.875) 4(0.75,0.875) 6(0.75,-0.875)
  rect 0.9x0.6 smd: 2(-0.85,0) 5(0.85,0)
LEDC1608X80M
  rect 1.1x1.05 smd: A(0.9,0) K(-0.9,0)
QFN50P500X500X100-33V2M
  oval 1x0.3 smd: 1(-2.5,1.75) 2(-2.5,1.25) 3(-2.5,0.75) 4(-2.5,0.25) 5(-2.5,-0.25) 6(-2.5,-0.75) 7(-2.5,-1.25) 8(-2.5,-1.75) 17(2.5,-1.75) 18(2.5,-1.25) 19(2.5,-0.75) 20(2.5,-0.25) 21(2.5,0.25) 22(2.5,0.75) 23(2.5,1.25) 24(2.5,1.75)
  oval 0.3x1 smd: 9(-1.75,-2.5) 10(-1.25,-2.5) 11(-0.75,-2.5) 12(-0.25,-2.5) 13(0.25,-2.5) 14(0.75,-2.5) 15(1.25,-2.5) 16(1.75,-2.5) 25(1.75,2.5) 26(1.25,2.5) 27(0.75,2.5) 28(0.25,2.5) 29(-0.25,2.5) 30(-0.75,2.5) 31(-1.25,2.5) 32(-1.75,2.5)
  rect 3.25x3.25 smd: 33(0,0)
QFN50P800X800X80-57M
  oval 0.9x0.3 smd: 1(-4,3.25) 2(-4,2.75) 3(-4,2.25) 4(-4,1.75) 5(-4,1.25) 6(-4,0.75) 7(-4,0.25) 8(-4,-0.25) 9(-4,-0.75) 10(-4,-1.25) 11(-4,-1.75) 12(-4,-2.25) 13(-4,-2.75) 14(-4,-3.25) 29(4,-3.25) 30(4,-2.75) 31(4,-2.25) 32(4,-1.75) 33(4,-1.25) 34(4,-0.75) 35(4,-0.25) 36(4,0.25) 37(4,0.75) 38(4,1.25) 39(4,1.75) 40(4,2.25) 41(4,2.75) 42(4,3.25)
  oval 0.3x0.9 smd: 15(-3.25,-4) 16(-2.75,-4) 17(-2.25,-4) 18(-1.75,-4) 19(-1.25,-4) 20(-0.75,-4) 21(-0.25,-4) 22(0.25,-4) 23(0.75,-4) 24(1.25,-4) 25(1.75,-4) 26(2.25,-4) 27(2.75,-4) 28(3.25,-4) 43(3.25,4) 44(2.75,4) 45(2.25,4) 46(1.75,4) 47(1.25,4) 48(0.75,4) 49(0.25,4) 50(-0.25,4) 51(-0.75,4) 52(-1.25,4) 53(-1.75,4) 54(-2.25,4) 55(-2.75,4) 56(-3.25,4)
  rect 6.7x6.7 smd: 57(0,0)
QFN80P400X400X80-13M
  oval 1.1x0.35 smd: 1(-1.9,0.8) 2(-1.9,0) 3(-1.9,-0.8) 7(1.9,-0.8) 8(1.9,0) 9(1.9,0.8)
  oval 0.35x1.1 smd: 4(-0.8,-1.9) 5(0,-1.9) 6(0.8,-1.9) 10(0.8,1.9) 11(0,1.9) 12(-0.8,1.9)
  rect 2.25x2.25 smd: 13(0,0)
RESC1005X50L
  rect 0.4x0.5 smd: 1(-0.45,0) 2(0.45,0)
RESC1608X90L
  rect 0.69x0.83 smd: 1(-0.67,0) 2(0.67,0)
SAMTEC_TSW-102-07-X-S
  rect 1.75x1.75 hole 1.15: 1(0,0)
  round 1.75 hole 1.15: 2(2.54,0)
SAMTEC_TSW-102-26-X-T
  rect 1.5x1.5 hole 0.9: 1(0,0)
  round 1.5 hole 0.9: 2(2.54,0) 3(0,-2.54) 4(2.54,-2.54) 5(0,-5.08) 6(2.54,-5.08)
SAMTEC_TSW-103-07-T-S
  rect 1.75x1.75 hole 1.15: 1(0,0)
  round 1.75 hole 1.15: 2(2.54,0) 3(5.08,0)
SOP65P490X110-8M
  rect 1.6x0.45 smd: 1(-2.35,0.975) 2(-2.35,0.325) 3(-2.35,-0.325) 4(-2.35,-0.975) 5(2.35,-0.975) 6(2.35,-0.325) 7(2.35,0.325) 8(2.35,0.975)
SOP65P640X120-14M
  rect 1.65x0.45 smd: 1(-3.05,1.95) 2(-3.05,1.3) 3(-3.05,0.65) 4(-3.05,0) 5(-3.05,-0.65) 6(-3.05,-1.3) 7(-3.05,-1.95) 8(3.05,-1.95) 9(3.05,-1.3) 10(3.05,-0.65) 11(3.05,0) 12(3.05,0.65) 13(3.05,1.3) 14(3.05,1.95)
SOT50P160X90-3M
  rect 1.05x0.4 smd: 1(-0.9,0.5) 2(-0.9,-0.5) 3(0.9,0)
SOT65P210X110-5M
  rect 1.1x0.45 smd: 1(-1.2,0.65) 2(-1.2,0) 3(-1.2,-0.65) 4(1.2,-0.65) 5(1.2,0.65)
SOT95P280X145-5M
  rect 1.25x0.65 smd: 1(-1.45,0.95) 2(-1.45,0) 3(-1.45,-0.95) 4(1.45,-0.95) 5(1.45,0.95)
SULLINS_PXC06SAAN
  rect 1.75x1.75 hole 1.15: 1(0,0)
  round 1.75 hole 1.15: 2(2.54,0) 3(5.08,0) 4(7.62,0) 5(10.16,0) 6(12.7,0)
SULLINS_PXC10SAAN
  rect 1.75x1.75 hole 1.15: 1(0,0)
  round 1.75 hole 1.15: 2(2.54,0) 3(5.08,0) 4(7.62,0) 5(10.16,0) 6(12.7,0) 7(15.24,0) 8(17.78,0) 9(20.32,0) 10(22.86,0)
SW_CL-SB-12B-1X
  round 0.8 hole 0.9 unplated: (0,3.4) (0,-3.4)
  rect 1.4x1.2 smd: 1(-2.2,2.5) 2(2.2,0) 3(-2.2,-2.5)
SW_EVQ-Q2X03W
  rect 3.2x1 smd: 1(-3.4,-2.5) 2(3.4,-2.5) 3(-3.4,2.5) 4(3.4,2.5)
TP_180P120D460H
  round 1.6 hole 1: 1(0,0)
TP_C25H12
  round 0.635 hole 0.305: 1(0,0)
TP_C127H81
  round 1.27 hole 0.813: 1(0,0)
TP_C240H180
  round 2.4 hole 1.8: 1(0,0)
TP_C340H160
  round 3.4 hole 1.6: 1(0,0)
TRAN_IRF_PQFN8_SINGLE_B
  rect 0.77x0.39 smd: 1(-1.54,0.975) 2(-1.54,0.325) 3(-1.54,-0.325) 4(-1.54,-0.975) 6(1.54,-0.325) 7(1.54,0.325) 8(1.54,0.975)
  custom 0.635x0.635 smd: 5(1.54,-0.975)
unnamed
  round 5.08 hole 3.175: (0,0)
XTAL320X250X070M
  rect 1.4x1.2 smd: 1(-1.1,-0.8) 2(1.1,-0.8) 3(1.1,0.8) 4(-1.1,0.8)

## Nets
+1.8V: C111.2 J101.2 R160.1 U103.5
+2.5V: C113.2 C151.1 R156.1 U100.40 U104.5
+3.3V: C115.2 C150.1 C157.2 C158.2 C221.2 C222.2 D100.A D101.A D102.A D103.A J100.2 J101.4 R100.2 R118.2 R158.1 R163.2 R214.2 R283.1 R293.2 R294.1 R295.2 R296.1 R297.2 R298.1 R299.2 R300.1 U100.2 U100.22 U102.5 U107.11 U205.7 U205.13(VDDIO)
BST: C4.1 U1.C5
CTSN: U100.39 U101.8
DCDN: U100.25 U101.7
DSRN: U100.24 U101.6
DTRN: U100.28 U101.31
EN_EXT: EN_EXT.1(TP1) J2.2 J100.5 Q1.1 R3.1
GPIO: GPIO.1(TP1) J2.3 J3.2 U1.B1
GROUND: C1.2 C2.1 C5.1 C6.1 C8.1 C9.1 C12.1 C13.2 C14.1 C17.1 C18.1 C19.1 C20.1 C21.1 C22.1 C23.1 C24.1 C25.1 C26.1 C27.1 C28.1 C29.1 C30.2 C31.1 C32.1 C33.1 C108.1 C110.1 C111.1 C112.1 C113.1 C114.2 C115.1 C118.1 C120.1 C150.2 C151.2 C152.1 C153.1 C154.1 C155.2 C156.1 C157.1 C158.1 C159.2 C200.1 C202.2 C204.1 C207.2 C208.1 C212.2 C214.1 C217.2 C218.1 C221.1 C222.1 C223.1 C239.1 C240.1 C241.1 C242.1 C248.1 C250.1 C251.1 GND1.1(TP1) GND2.1 GND3.1 GND4.1 GND5.1(TP1) GND6.1(TP1) GND7.1(TP1) GND8.1 J2.10 J3.3 J4.3 J6.5 J100.6 L2.1 L2.2 L3.1 L3.2 L4.1 L4.2 L5.1 L5.2 Q1.2(S) R1.2 R3.2 R110.2 R115.2 R122.2 R157.2 R159.2 R206.1 R208.2 R210.1 R211.2 R226.1 R230.2 R231.1 R233.2 R240.1 R243.2 R244.1 R245.2 R252.1 R255.2 R257.1 R258.2 SW1.4 SW2.3 U1.B3 U1.C3 U1.D1 U1.D2 U1.E1 U1.E5 U100.1 U100.3 U100.4 U100.23 U100.35 U101.4 U101.17 U101.20 U101.24 U101.26 U101.33 U102.2 U103.2 U104.2 U107.5 U107.13 U108.2 U108.5(WP) U200.4 U201.4 U202.4 U203.4 U205.4 U205.8 U205.9 Y101.2 Y101.4
INLDO: C13.1 C18.2 INLDO.1(TP1) R11.1 U1.B6
ISET_LDO: R250.1 U205.6
ISET_SBB0: R203.1 U205.2
ISET_SBB1: R224.1 U205.3
ISET_SBB2: R237.1 U205.5
LDO: C5.2 C17.2 C23.2 C25.2 C33.2 J101.6 J207.2 LDO.1(TP1) U1.B5
LED0: LED0.1(TP1) R7.2 U1.A6
LED1: LED1.1(TP1) R8.2 U1.A5
LED2: LED2.1(TP1) R6.2 U1.A4
LXA: L1.2 U1.D4
LXB: C4.2 L1.1 U1.D5
MAXQP03: PO3.1(TP1) U100.52
MAXQP05: PO5.1(TP1) U100.54
NEN: J2.5 J5.2 NEN.1(TP1) U1.A2
NIRQ: J2.6 NIRQ.1(TP1) R14.1 R150.2 U1.C2
NIRQ1: PO0.1(TP1) R152.1 U100.49
NRST: J2.7 J8.1 NRST.1(TP1) R10.1 U1.B2
P01: PO1.1(TP1) U100.50
P02: PO2.1(TP1) U100.51
P04: PO4.1(TP1) U100.53
P06: PO6.1(TP1) U100.55
P07: PO7.1(TP1) U100.56
PWRHLD: J2.4 J4.2 PWRHLD.1(TP1) R16.1 U1.A1
RIN: U100.27 U101.3
RTSN: U100.26 U101.32
RXD: U100.43 U101.2
SBB0: C2.2 C9.2 C19.2 C21.2 C27.2 J201.2 R11.2 SBB0.1(TP1) U1.C6
SBB1: C8.2 C20.2 C22.2 C28.2 C31.2 J203.2 SBB1.1(TP1) U1.D6
SBB2: C6.2 C24.2 C26.2 C29.2 C32.2 J205.2 SBB2.1(TP1) U1.E6
SCL: J2.8 R107.2 R136.2 SCL.1(TP1) U1.B4
SCL1: J100.3 R118.1 R155.2 R162.1 R305.1 U107.9
SDA: J2.9 R108.2 R135.2 SDA.1(TP1) U1.A3
SDA1: J100.4 R100.1 R148.2 R164.2 R306.1 U107.10
TXD: U100.44 U101.30
UNNAMED_1_CL-SB-12B-1X_I99_2: J5.1 SW2.2
UNNAMED_1_EKCAPNP_I69_2: C12.2 R17.1 U1.C4(VIO)
UNNAMED_1_EKRESSMD_I59_1: DS1.1 R7.1
UNNAMED_1_EKRESSMD_I60_1: DS1.2 R8.1
UNNAMED_1_EKRESSMD_I61_1: DS1.3(C_3) R6.1
UNNAMED_1_EKRESSMD_I72_2: DS1.4 DS1.5 DS1.6 R9.2
UNNAMED_1_EVQ-Q2XXXX_I7_1: J5.3 Q1.3 R2.1 SW1.1
UNNAMED_1_HEADER2P_I92_2: J8.2 R16.2
UNNAMED_4_10103592-0001LF_I2_1: C155.1 FB100.1 J6.1
UNNAMED_4_10103592-0001LF_I2_2: J6.2 R123.1
UNNAMED_4_10103592-0001LF_I2_3: J6.3 R103.1
UNNAMED_4_10103592-0001LF_I2_SHIELD10: J6.6 J6.7 J6.8 J6.9(SHIELD9) J6.10 J6.11 R122.1 R142.1
UNNAMED_4_CAPNP_I101_2: C153.2 U100.41 Y101.3(P2)
UNNAMED_4_CAPNP_I105_2: C152.2 U100.42 Y101.1
UNNAMED_4_EKCAPNP_I12_1: C156.2 C159.1 U101.1(VCCIO) U101.16
UNNAMED_4_EKCAPNP_I29_1: C114.1 R142.2
UNNAMED_4_EKRESSMD_I15_2: R123.2 U101.15
UNNAMED_4_EKRESSMD_I16_2: R103.2 U101.14
UNNAMED_4_EKRESSMD_I17_1: R111.1 U101.22
UNNAMED_4_EKRESSMD_I17_2: D100.K(B) R111.2
UNNAMED_4_EKRESSMD_I18_1: R109.1 U101.21
UNNAMED_4_EKRESSMD_I18_2: D101.K(B) R109.2
UNNAMED_4_EKRESSMD_I87_1: R150.1 U107.3
UNNAMED_4_EKRESSMD_I109_1: R155.1 U100.36
UNNAMED_4_EKRESSMD_I113_1: R148.1 U100.37
UNNAMED_4_EKRESSMD_I153_1: R135.1 U107.1
UNNAMED_4_EKRESSMD_I154_1: R136.1 U107.2
UNNAMED_4_EKRESSMD_I171_2: R143.2 U107.6
UNNAMED_4_EKRESSMD_I174_1: R156.2 R157.1 U104.4
UNNAMED_4_EKRESSMD_I177_1: R158.2 R159.1 U102.4
UNNAMED_4_EKRESSMD_I190_2: R152.2 R161.2 U107.8
UNNAMED_4_LED_I7_B: D102.K(B) R110.1
UNNAMED_4_LED_I189_B: D103.K(B) R161.1
UNNAMED_4_MAX8512_I5_FB: R1.1 R160.2 U103.4
UNNAMED_6_24AA02_I452_SCL: R162.2 U108.1
UNNAMED_6_24AA02_I452_SDA: R164.1 U108.3
UNNAMED_6_24AA02_I452_VCC: C14.2 R163.1 U108.4
UNNAMED_6_CAPNP_I21_1: C203.1 R202.2 R205.1 U200.7(OUTB)
UNNAMED_6_CAPNP_I271_2: C208.2 R226.2 R229.1 R295.1 U201.5
UNNAMED_6_CAPNP_I277_1: C209.1 R223.2 R228.1 U201.7(OUTB)
UNNAMED_6_CAPNP_I277_2: C209.2 R228.2 R230.1 R296.2 U201.6
UNNAMED_6_CAPNP_I289_2: C248.2 R224.2 U201.3
UNNAMED_6_CAPNP_I307_2: C214.2 R240.2 R242.1 R297.1 U202.5
UNNAMED_6_CAPNP_I311_1: C213.1 R236.2 R239.1 U202.7(OUTB)
UNNAMED_6_CAPNP_I311_2: C213.2 R239.2 R243.1 R298.2 U202.6
UNNAMED_6_CAPNP_I323_2: C250.2 R237.2 U202.3
UNNAMED_6_CAPNP_I341_2: C218.2 R252.2 R254.1 R299.1 U203.5
UNNAMED_6_CAPNP_I345_1: C219.1 R249.2 R253.1 U203.7(OUTB)
UNNAMED_6_CAPNP_I345_2: C219.2 R253.2 R255.1 R300.2 U203.6
UNNAMED_6_CAPNP_I357_2: C251.2 R250.2 U203.3
UNNAMED_6_CAPNP_I359_2: C200.2 R203.2 U200.3
UNNAMED_6_EKCAPNP_I10_1: C201.1 R202.1 U200.2
UNNAMED_6_EKCAPNP_I10_2: C201.2 R201.1
UNNAMED_6_EKCAPNP_I203_2: C223.2 U205.1
UNNAMED_6_EKCAPNP_I237_2: C239.2 J201.1 Q200.5 Q200.6 Q200.7 Q200.8
UNNAMED_6_EKCAPNP_I261_2: C240.2 J203.1 Q201.5 Q201.6 Q201.7 Q201.8
UNNAMED_6_EKCAPNP_I287_1: C206.1 R223.1 U201.2
UNNAMED_6_EKCAPNP_I287_2: C206.2 R222.1
UNNAMED_6_EKCAPNP_I298_2: C241.2 J205.1 Q202.5 Q202.6 Q202.7 Q202.8
UNNAMED_6_EKCAPNP_I321_1: C211.1 R236.1 U202.2
UNNAMED_6_EKCAPNP_I321_2: C211.2 R235.1
UNNAMED_6_EKCAPNP_I332_2: C242.2 J207.1 Q203.5 Q203.6 Q203.7 Q203.8
UNNAMED_6_EKCAPNP_I355_1: C216.1 R249.1 U203.2
UNNAMED_6_EKCAPNP_I355_2: C216.2 R248.1
UNNAMED_6_EKRESSMD_I42_1: C204.2 R206.2 R207.1 R293.1 U200.5
UNNAMED_6_EKRESSMD_I42_2: Q200.1 Q200.2 Q200.3(S3) R207.2 R211.1 VIL_SBB0.1(TP1)
UNNAMED_6_EKRESSMD_I43_1: C203.2 R205.2 R208.1 R294.2 U200.6
UNNAMED_6_EKRESSMD_I99_1: R201.2 R204.1 U200.1
UNNAMED_6_EKRESSMD_I99_2: J200.1 R204.2
UNNAMED_6_EKRESSMD_I207_1: R214.1 U205.14
UNNAMED_6_EKRESSMD_I222_2: R283.2 U205.12
UNNAMED_6_EKRESSMD_I273_2: Q201.1 Q201.2 Q201.3(S3) R229.2 R233.1 VIL_SBB1.1(TP1)
UNNAMED_6_EKRESSMD_I278_1: R222.2 R225.1 U201.1
UNNAMED_6_EKRESSMD_I278_2: J202.1 R225.2
UNNAMED_6_EKRESSMD_I306_2: Q202.1 Q202.2 Q202.3(S3) R242.2 R245.1 VIL_SBB2.1(TP1)
UNNAMED_6_EKRESSMD_I313_1: R235.2 R238.1 U202.1
UNNAMED_6_EKRESSMD_I313_2: J204.1 R238.2
UNNAMED_6_EKRESSMD_I340_2: Q203.1 Q203.2 Q203.3(S3) R254.2 R258.1 VIL_LDO.1(TP1)
UNNAMED_6_EKRESSMD_I347_1: R248.2 R251.1 U203.1
UNNAMED_6_EKRESSMD_I347_2: J206.1 R251.2
UNNAMED_6_EKRESSMD_I450_2: R305.2 U205.10
UNNAMED_6_EKRESSMD_I451_2: R306.2 U205.11
UNNAMED_6_HEADER2P_I444_2: J202.2 Q201.4 R231.2
UNNAMED_6_HEADER2P_I446_2: J204.2 Q202.4 R244.2
UNNAMED_6_HEADER2P_I448_2: J206.2 Q203.4 R257.2
UNNAMED_6_RESSMD_I28_2: J200.2 Q200.4 R210.2
VIO: C120.2 J2.1 J3.1 J4.1 J101.1 J101.3 J101.5 R10.2 R14.2 R17.2 R107.1 R108.1 R143.1 U107.12(VL)
VSYS: C1.1 C30.1 R2.2 R9.1 SW2.1 U1.E2 U1.E3 U1.E4 VSYS.1(TP1)
VUSB: C108.2 C110.2 C112.2 C118.2 C154.2 C202.1 C207.1 C212.1 C217.1 FB100.2 J100.1 R115.1 U101.19 U102.1 U102.3(SHDN*) U103.1 U103.3(SHDN*) U104.1 U104.3(SHDN*) U200.8 U201.8 U202.8 U203.8

Pads without a net: J6 4; SW1 2 3; U1 C1 D3; U100 5 6 7 8 9 10 11 12 13 14 15 16 17 18 19 20 21 29 30 31 32 33 34 38 45 46 47 48 57; U101 5 9 10 11 12 13 18 23 25 27 28 29; U107 4 7

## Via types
v1: diameter 0.457, hole 0.203, TOP to BOTTOM, 345 vias
v2: diameter 0.203, hole 0.102, TOP to INTERNAL2, 47 vias

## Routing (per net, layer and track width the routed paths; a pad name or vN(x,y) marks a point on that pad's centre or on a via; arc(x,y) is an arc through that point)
+1.8V: length 42.8
  BOTTOM w0.381: R160.1 6.48,90.83 7.06,91.41 9.84,91.41 10.15,91.11 ; 10.15,91.11 26.14,91.11 27.91,92.89 43.51,92.89 J101.2 ; 10.15,91.11 C111.2 10.15,90.12 10.12,90.09 U103.5
+2.5V: length 34.3
  TOP w0.381: v1(32.92,74.98) v1(21.62,74.98)
  INTERNAL3 w0.381: v1(21.62,74.98) v1(21.62,89.18)
  BOTTOM w0.254: U100.40 33.7,73.96 33.54,74.12 C151.1
  BOTTOM w0.381: C113.2 18.25,90.13 R156.1 ; C113.2 18.25,88.65 17.79,88.19 U104.5 ; C113.2 18.89,89.31 19.02,89.18 v1(21.62,89.18) ; C151.1 33.2,74.7 v1(32.92,74.98)
+3.3V: length 246.4
  TOP w0.254: D101.A 16.85,80.91 16.89,80.95 D100.A
  TOP w0.381: v1(43.66,79.02) v1(31.39,79.02) v1(28.73,79.02) ; v1(23.93,80.9) 19.5,80.9 19.45,80.95 D100.A ; D103.A v1(43.64,81.25) ; v1(43.66,83.97) 48.67,83.97 48.69,83.99 v1(49.36,83.99) 55.14,83.99 ; 55.14,83.99 55.16,84 v1(55.42,84) ; 55.14,83.99 v1(60.26,83.99) ; D102.A 50.4,88.21 v1(49.28,88.21) ; v1(34.2,63.37) v1(23.97,63.37) ; v1(28.73,84.86) v1(23.93,84.86)
  INTERNAL3 w0.254: v1(71.98,29.9) 71.98,31.56 v1(70.92,32.61) 70.92,36.73 v1(71.73,37.54) v1(71.73,39.75) ; v1(65.1,83.99) v1(65.1,82.03)
  INTERNAL3 w0.381: J100.2 v1(55.42,84) ; 65.89,51.64 65.89,42.37 65.63,42.11 v1(65.63,41.17) v1(65.63,32.77) ; 65.89,51.64 65.89,67.34 65.94,67.39 v1(65.94,68.12) ; 65.89,51.64 v1(65.91,51.64) ; J101.4 42.24,87.96 43.71,86.49 43.71,84.7 43.66,84.65 v1(43.66,83.97) 43.66,81.13 ; v1(49.36,83.99) 49.36,87.45 49.28,87.54 v1(49.28,88.21) ; v1(43.64,81.25) 43.64,81.15 43.66,81.13 ; 43.66,81.13 v1(43.66,79.02) ; v1(70.93,66.79) v1(70.93,64.18) ; v1(71.36,49.24) v1(71.36,47.91) ; v1(23.97,63.37) 23.97,67.18 23.94,67.21 v1(23.94,67.88) 23.94,68.55 23.94,68.56 23.94,72.15 23.93,72.16 v1(23.93,80.9) v1(23.93,84.86) ; v1(60.58,68.12) 60.58,73.86 60.26,74.18 v1(60.26,74.88) v1(60.26,83.99)
  BOTTOM w0.254: U107.11 28.99,84.7 C115.2 v1(28.73,84.86) 28.73,85.34 C157.2 ; v1(65.1,82.03) 65.1,80.97 U205.13 ; 64.49,83.99 v1(65.1,83.99) ; 64.49,83.99 v1(60.26,83.99) ; 64.49,83.99 64.48,83.98 R283.1 ; v1(65.1,83.99) 65.2,84.08 C221.2 ; v1(65.1,83.99) 65.63,83.46 R214.2 ; R298.1 v1(71.98,29.9) ; 60.48,74.85 60.45,74.88 v1(60.26,74.88) ; 60.48,74.85 60.26,74.85 60.22,74.81 C222.2 ; 60.48,74.85 U205.7 ; v1(71.73,37.54) 71.73,37.63 R296.1 ; v1(71.73,39.75) 71.52,39.54 R295.2 ; R118.2 32.42,78.33 R100.2 ; U100.22 27.1,68.8 26.24,67.94 25.81,67.94 C150.1 v1(23.94,67.88) ; U100.2 v1(34.2,63.37)
  BOTTOM w0.381: C115.2 v1(28.73,79.02) ; R300.1 70.45,64.18 v1(70.93,64.18) ; R294.1 70.9,47.91 v1(71.36,47.91) ; v1(65.63,41.17) 69.99,41.17 71.31,39.85 R295.2 ; U102.5 48.54,88.16 C158.2 ; C158.2 48.5,88.85 48.12,89.23 45.82,89.23 45.53,88.93 R158.1 ; C158.2 v1(49.28,88.21) ; R297.2 71.47,32.06 v1(70.92,32.61) 70.24,32.61 70.09,32.77 v1(65.63,32.77) ; v1(71.36,49.24) R293.2 70.92,49.88 69.22,51.59 66.64,51.59 66.59,51.64 v1(65.91,51.64) ; v1(31.39,79.02) 31.39,78.34 R118.2 ; R163.2 43.7,78.1 43.66,78.14 v1(43.66,79.02) ; v1(60.58,68.12) v1(65.94,68.12) 69.93,68.12 70.43,67.61 R299.2 v1(70.93,66.79)
BST: length 4.5
  INTERNAL2 w0.254: v2(50.24,38.56) 49.61,38.56 48.69,39.47 48.69,40.83 48.06,41.45 v2(47.69,41.45)
CTSN: length 26.5
  TOP w0.254: v1(14.84,68) 15.7,68 16.41,68.71 v1(24.89,68.71) ; v1(25.2,73.89) v1(32.79,73.89)
  INTERNAL3 w0.254: v1(24.89,68.71) 24.89,68.94 25.2,69.24 v1(25.2,73.89)
  BOTTOM w0.254: v1(32.79,73.89) 33.2,73.48 U100.39 ; U101.8 v1(14.84,68)
DCDN: length 13.9
  TOP w0.254: v1(15.32,68.66) 15.54,68.66 16.23,69.34 24.18,69.34 v1(24.61,69.77)
  BOTTOM w0.254: U101.7 15.32,69.72 v1(15.32,68.66) ; U100.25 25.27,70.3 25.17,70.21 25.04,70.21 v1(24.61,69.77)
DSRN: length 17.9
  TOP w0.254: v1(15.84,66.51) v1(25.84,66.51)
  INTERNAL3 w0.254: v1(25.84,66.51) v1(25.84,69.48)
  BOTTOM w0.254: U101.6 v1(15.84,66.51) ; v1(25.84,69.48) 26.07,69.48 26.37,69.77 26.51,69.77 26.55,69.8 U100.24
DTRN: length 8.7
  BOTTOM w0.254: U100.28 22.94,71.8 22.92,71.78 22.07,71.78 21.28,70.99 U101.31
EN_EXT: length 118.7
  TOP w0.254: v1(5.99,39.7) 4.2,39.7 4.16,39.74 J2.2 ; Q1.1 8.35,66.94 8.31,66.9 R3.1 v1(6.7,66.9) ; v1(9.02,92.46) 10.9,92.46 11.71,91.64 36.32,91.64 37.62,92.94 47.09,92.94 47.45,92.58 61.59,92.58 J100.5
  INTERNAL3 w0.254: v1(5.99,39.7) 5.99,59.74 6.7,60.45 v1(6.7,66.9) 6.7,83.97 v1(6.78,84.05) 6.78,90.22 v1(9.02,92.46)
  BOTTOM w0.254: EN_EXT.1 5.36,84.04 5.38,84.05 v1(6.78,84.05)
GPIO: length 73.2
  TOP w0.152: v1(14.66,42.87) 15.52,42.87 15.87,42.52 44.98,42.52 45.66,41.85 U1.B1 ; 12.03,37.21 4.13,37.21 4.11,37.2 J2.3 ; 12.03,37.21 12.01,37.23 GPIO.1 ; 12.03,37.21 v1(14.81,37.21)
  INTERNAL3 w0.152: v1(14.66,42.87) 14.66,42.31 14.81,42.16 v1(14.81,37.21) 14.81,26.49 12.56,24.24 J3.2
GROUND: length 81.7
  TOP w0.152: 47.69,40.49 U1.E5 ; U1.D1 45.83,41.05 ; U1.B3 v2(46.89,41.45) ; U1.E1 45.83,40.65
  TOP w0.254: 49.98,39.73 49.98,40.11 C6.1 ; Q1.2 8.37,65.94 8.31,66 R3.2 ; 47.69,40.39 47.69,40.49
  TOP w0.381: 50.06,41.77 C9.1 50.06,41.82 C8.1 ; v1(50.06,43.36) C5.1 ; C241.1 84.55,33.56 ; C242.1 85.01,62.02 ; C239.1 v1(85.22,49.28)
  TOP w0.508: SW2.3 1.11,58.03 v1(2,57.14)
  INTERNAL2 w0.102: v2(46.89,41.45) 46.89,41.55 46.78,41.66 46.78,42.09
  BOTTOM w0.127: R233.2 85.34,42.33 85.25,42.42 84.68,42.42 83.55,41.29 80.05,41.29 79.31,42.03 R230.2 ; R255.2 83.48,62.7 84.25,63.47 85.17,63.47 85.21,63.43 85.22,63.43 R258.2 ; R243.2 78.9,34.52 79.79,34.52 80.27,34.04 83.57,34.04 85.04,35.51 85.48,35.51 85.6,35.39 85.6,34.98 ; R211.2 85.35,50.62 85.28,50.69 84.65,50.69 83.09,49.14 R208.2
  BOTTOM w0.254: R210.1 v1(91.76,53.12) ; U101.26 v1(21.26,73.49) ; U101.24 v1(19.06,74.74) ; R257.1 v1(91.18,67.03) ; C150.2 26.18,68.78 v1(26.49,69.09) 26.71,69.3 U100.23 ; v1(61.23,80.95) U205.8 U205.9 ; v1(15.53,77.81) C108.1 15.75,77.34 16.34,76.76 U101.20 ; U101.17 v1(14.29,74.74) ; C223.1 v1(66.41,71.97) ; C222.1 v1(59.62,73.42) ; v1(63.48,72.83) 63.48,73.13 63.82,73.48 U205.4
  BOTTOM w0.381: v1(85.22,49.28) 85.22,49.88 R211.2 ; 7.9,90.42 7.61,90.14 R1.2 ; v1(16.23,88.98) 16.54,89.28 R157.2 17.32,89.28 C113.1 ; U108.2 v1(51.78,78.35) ; C251.1 60.84,65.92 v1(60.86,65.94) ; R159.2 v1(46.29,88.41) ; R110.2 v1(50.38,86.52) ; v1(61.44,29.84) 61.43,29.84 ; U104.2 17.14,84.73 16.85,84.44 C112.1 ; C14.1 45.83,78.93 46.2,79.3 46.21,79.3 U108.5 ; v1(91.24,42.51) 91.21,42.55 R231.1 ; C158.1 v1(47.1,88.21) ; C13.2 48.59,43.21 49.28,43.21 49.3,43.22 49.89,43.22 50.03,43.36 v1(50.06,43.36) ; C111.1 v1(8.29,90.43) ; R244.1 92.94,38.48 93.31,38.85 ; U102.2 47.89,83.81 47.65,83.56 C118.1 v1(46.95,83.26) ; U101.4 16.84,68.77 16.43,68.37 v1(16.43,67.7) ; v1(8.39,85.26) C110.1 9.23,85.56 9.47,85.8 U103.2
  BOTTOM w0.457: 6.39,72.26 J6.5
  BOTTOM w0.508: 6.53,72.14 6.41,72.26 6.39,72.26 ; C114.2 R122.2 6.85,72.12
  vias: v1(2.55,44.65) v1(3.15,55.07) v1(3.25,67.97) v1(21.2,93.86) v1(21.78,93.85) v1(23.46,32.9) v1(24.04,32.89) v1(24.68,47.02) v1(25.26,47.01) v1(29.74,22.1) v1(30.24,52.76) v1(30.31,22.1) v1(30.82,52.75) v1(42.59,40.77) v1(42.59,40.17) v1(42.61,39.53) v1(43.17,40.78) v1(43.19,40.16) v1(43.19,39.52) v1(45.34,14.2) v1(45.41,81.84) v1(45.38,16.82) v1(45.38,15.65) v1(45.92,64.09) v1(45.86,47.49) v1(45.86,46.89) v1(45.88,46.25) v1(45.98,81.84) v1(46.49,64.08) v1(46.47,47.51) v1(46.48,46.87) v1(46.45,46.27) v1(46.53,18.19) v1(46.57,16.86) v1(46.58,15.6) v1(46.62,14.27) v1(47.44,34.22) v1(47.84,18.18) v1(47.84,16.91) v1(48.01,34.21) v1(49.18,47.49) v1(49.18,46.89) v1(49.17,46.27) v1(49.79,47.51) v1(49.8,46.87) v1(49.77,46.27) v1(51.15,81.67) v1(51.72,81.66) v1(53.41,14.79) v1(53.59,74) v1(53.98,14.78) v1(54.16,73.99) v1(58.57,42.11) v1(60.81,49.94) v1(60.78,40.64) v1(63.68,66.52) v1(63.68,50.47) v1(64.47,40.74) v1(64.92,34.44) v1(65.1,29.03) v1(65.13,26.39) v1(65.23,50.8) v1(65.23,49.68) v1(66.14,68.88) v1(68.25,44.4) v1(68.33,60.83) v1(68.44,43.22) v1(68.42,41.89) v1(68.73,34.54) v1(68.91,26.44) v1(69.65,41.89) v1(69.67,43.22) v1(70.82,41.66) v1(71.34,78.01) v1(71.32,41.05) v1(71.63,61.57) v1(71.63,60.86) v1(71.7,15.5) v1(71.83,40.64) v1(71.83,33.17) v1(71.92,78) v1(71.97,58.13) v1(71.97,57.21) v1(72.27,15.49) v1(72.44,60.86) v1(73.21,58.13) v1(73.21,57.21) v1(73.86,61.47) v1(73.99,33.5) v1(74.47,41.15) v1(74.68,61.47) v1(74.75,33.5) v1(74.88,49.28) v1(74.98,41.66) v1(75.13,35.69) v1(75.13,34.87) v1(75.13,34.11) v1(75.18,62.69) v1(75.18,61.98) v1(75.29,50.5) v1(75.29,49.78) v1(75.29,42.27) v1(78.78,71.05) v1(80.05,15.5) v1(80.63,15.49) v1(81.45,89.16) v1(81.48,61.26) v1(81.58,57.71) v1(81.58,53.75) v1(81.66,40.51) v1(82.02,89.15) v1(85.09,62.1) v1(85.85,49.28) v1(85.98,63.12) v1(85.98,62.48) v1(85.98,49.91) v1(85.98,42.24) v1(85.98,41.63) v1(86.23,35.05) v1(86.23,34.42) v1(86.66,54.05) v1(91.53,85.32) v1(91.53,71.73) v1(92.11,85.32) v1(92.11,71.73) v1(93.34,38.89) v1(93.98,47.96) v1(93.98,38.91) v2(46.49,41.05) v2(49.36,39.68) v2(49.38,39.33) v2(49.68,39.68) v2(49.68,39.34) v2(50,41.99) v2(50,41.71) v2(49.99,39.69) v2(50,39.34) v2(50.08,41.13) v2(50.08,40.77) v2(50.08,40.31) v2(50.08,40.03) v2(50.38,42.01) v2(50.38,41.66) v2(50.38,41.12) v2(50.38,40.77) v2(50.39,40.33) v2(50.38,40.03) v2(50.37,39.69) v2(50.4,39.36) v2(50.7,42) v2(50.7,41.66) v2(50.7,41.11) v2(50.7,40.77)
INLDO: length 36
  TOP w0.203: U1.B6 48.2,41.85 48.54,42.19 48.56,42.19 v1(48.59,42.21)
  TOP w0.254: 50.7,42.6 v1(50.83,42.6)
  TOP w0.381: C18.2 74.97,53.73 74.98,53.72
  TOP w0.508: v1(50.83,42.6) 52.2,43.97 52.2,44.07
  TOP w1.27: INLDO.1 76.41,53.69 76.37,53.72 61.85,53.72 52.2,44.07
  BOTTOM w0.381: v1(50.83,42.6) 50.77,42.65 R11.1 49.25,42.65 48.82,42.21 v1(48.59,42.21)
ISET_LDO: length 11.7
  INTERNAL3 w0.254: v1(59.66,72.67) v1(59.66,66.24)
  BOTTOM w0.254: v1(59.66,72.67) 61.55,72.67 62.52,73.65 U205.6 ; R250.1 59.66,65.54 v1(59.66,66.24)
ISET_SBB0: length 31.4
  INTERNAL3 w0.254: v1(59.88,50) 59.88,52.13 59.87,52.15 v1(59.87,53.11) ; v1(65.12,73.29) 65.12,52.89 65.1,52.86 v1(65.1,52.63)
  BOTTOM w0.254: v1(65.1,52.63) 64.62,53.11 v1(59.87,53.11) ; U205.2 v1(65.12,73.29) ; R203.1 v1(59.88,50)
ISET_SBB1: length 40.6
  INTERNAL3 w0.254: v1(64.47,42.24) 64.47,42.54 64.47,42.55 v1(64.47,72.55) ; v1(59.92,39.75) v1(59.92,42.24)
  BOTTOM w0.254: v1(59.92,42.24) v1(64.47,42.24) ; R224.1 59.92,38.83 v1(59.92,39.75) ; U205.3 v1(64.47,72.55)
ISET_SBB2: length 47.4
  INTERNAL3 w0.254: v1(62.74,73.11) 62.74,33.66 59.74,30.66 v1(58.88,30.66)
  BOTTOM w0.254: v1(62.74,73.11) 63.17,73.54 U205.5 ; R237.1 59.78,30.66 v1(58.88,30.66)
LDO: length 117.3
  TOP w0.254: C17.2 73.13,59.88 73.54,59.48
  TOP w0.381: C5.2 49.16,44.13 49.59,44.56
  TOP w1.27: 49.59,44.56 50.26,45.23 50.3,45.23 64.55,59.48 LDO.1 83.24,59.48 83.8,58.91 85.57,58.91 85.58,58.92 J207.2
  INTERNAL2 w0.254: v2(49.09,42.64) 49.03,42.7 48.03,42.7 47.69,42.36 v2(47.69,41.85)
  INTERNAL3 w0.381: LDO.1 78.41,68.68 77.8,69.29 77.8,89.56 77.9,89.66 v1(77.9,90.32)
  BOTTOM w0.381: J101.6 41,90.32 v1(77.9,90.32)
LED0: length 19
  TOP w0.152: U1.A6 48.16,42.32 48.16,42.38 48.39,42.61 48.39,43.03
  TOP w0.229: 49.19,57.54 R7.2
  TOP w0.254: 49.19,57.54 48.22,57.54 LED0.1 ; 48.39,43.03 48.39,43.56 48.57,43.74 v1(48.57,44.97)
  INTERNAL3 w0.305: 48.26,57.56 48.2,57.56 LED0.1
  INTERNAL3 w0.356: v1(48.57,44.97) 48.57,45.1 48.56,45.1 48.56,57.25 48.26,57.56
LED1: length 19
  TOP w0.152: U1.A5 47.9,42.47 47.9,42.49 48,42.58 48,42.96 47.99,42.97
  TOP w0.254: v1(47.83,45.7) 47.83,43.93 47.99,43.76 47.99,42.97
  TOP w0.33: R8.2 48.36,56.18 48.33,56.15 LED1.1
  INTERNAL3 w0.305: LED1.1 47.73,54.73 47.73,46.44 47.83,46.34 v1(47.83,45.7)
LED2: length 18.1
  TOP w0.152: U1.A4 47.6,42.56 47.6,43.06 47.58,43.08
  TOP w0.254: v1(47.09,44.78) 47.09,43.99 47.58,43.5 47.58,43.08
  TOP w0.381: LED2.1 46.39,54.95 R6.2
  INTERNAL3 w0.279: 47.09,52.6 v1(47.09,44.78)
  INTERNAL3 w0.305: 47.09,52.6 47.09,52.72 LED2.1
LXA: length 3.8
  TOP w0.254: v2(46.73,37.81) 46.73,37.91 46.85,38.04 ; 47.01,37.88 v2(47.01,37.81) ; 47.02,38.13 v2(47.02,38.1) v2(46.73,38.1)
  INTERNAL2 w0.254: v2(47.29,41.05) 47.29,40.58
  INTERNAL2 w0.508: 47.29,40.58 47.29,38.83 46.94,38.48 46.94,38.19 v2(47.02,38.1)
LXB: length 5.4
  TOP w0.254: v2(48.52,38.22) 48.2,38.22 v2(48.2,38.22) ; v2(48.2,37.89) 48.2,37.89 v2(48.53,37.89)
  TOP w0.381: L1.1 48.74,37.68 C4.2
  INTERNAL2 w0.254: v2(47.69,41.05) 48.05,40.69
  INTERNAL2 w0.508: v2(48.2,38.22) 48.25,38.28 48.25,38.7 48.05,38.89 48.05,40.69
MAXQP03: length 3.5
  BOTTOM w0.254: U100.52 37.34,67.3 37.4,67.36 PO3.1
MAXQP05: length 3.8
  BOTTOM w0.254: U100.54 36.31,66.3 36.32,66.3 36.68,66.3 37.51,65.47 PO5.1
NEN: length 81.4
  TOP w0.152: U1.A2 45.46,43.28 22.35,43.28 20.02,45.62 v1(19.41,45.62) ; v1(9.47,32.07) 8.92,32.07 8.87,32.12 J2.5
  TOP w0.254: v1(9.52,59.61) 10.13,59.61 10.16,59.64 10.87,59.64 11.3,60.06 J5.2 ; v1(19.41,45.62) v1(9.45,45.62)
  INTERNAL3 w0.152: 9.52,45.72 9.45,45.65 v1(9.45,45.62) ; 9.52,45.72 v1(9.52,59.61) ; 9.52,45.72 9.52,32.68 9.47,32.63 v1(9.47,32.07) ; v1(19.41,45.62) 19.41,46.28 19.47,46.34 NEN.1
NIRQ: length 111.3
  TOP w0.152: J2.6 9.54,29.58 NIRQ.1 ; v1(13.24,41.14) v1(27.74,41.14) 39.12,41.14 39.12,41.15 40.87,41.15 41.17,41.45 v2(45.39,41.45)
  INTERNAL2 w0.152: v2(46.49,41.45) v2(45.39,41.45)
  INTERNAL3 w0.152: NIRQ.1 13.24,33.28 v1(13.24,41.14)
  INTERNAL3 w0.254: v1(27.74,41.14) v1(27.74,90.96)
  BOTTOM w0.254: v1(27.74,90.96) 33.32,90.96 33.96,90.32 33.96,89.85 33.95,89.84 R150.2 33.96,89.27 R14.1
NIRQ1: length 18.3
  INTERNAL3 w0.254: PO0.1 37.65,71.22 37.62,71.24 v1(37.62,80.37)
  BOTTOM w0.254: R152.1 36.99,80.35 37.01,80.37 v1(37.62,80.37) ; U100.49 35.93,68.8 PO0.1
NRST: length 68.4
  TOP w0.152: v2(45.03,41.85) 41.06,41.85 40.87,41.66 14.57,41.66 14.55,41.68 v1(14,41.68)
  TOP w0.254: R10.1 10.73,27.02 10.74,27.04 ; v1(14,27.06) 13.2,27.06 13.16,27.09 NRST.1 10.8,27.09 10.74,27.04 ; 10.74,27.04 J2.7
  INTERNAL2 w0.152: v2(46.49,41.85) v2(45.03,41.85)
  INTERNAL3 w0.152: v1(14,41.68) v1(14,27.06)
  INTERNAL3 w0.254: 13.92,49.83 13.92,42.36 14,42.29 v1(14,41.68)
  INTERNAL3 w0.381: 13.92,49.83 13.93,49.85 J8.1
P01: length 4.1
  BOTTOM w0.254: PO1.1 38.19,69.8 36.7,68.3 U100.50
P02: length 2.4
  BOTTOM w0.254: PO2.1 37.17,67.8 U100.51
P04: length 2.4
  BOTTOM w0.254: PO4.1 37.36,66.8 U100.53
P06: length 2.8
  BOTTOM w0.254: PO6.1 37.6,64.85 37.29,64.85 36.33,65.8 U100.55
P07: length 4.1
  BOTTOM w0.254: PO7.1 37.27,63.78 35.75,65.3 U100.56
PWRHLD: length 105.2
  TOP w0.152: J2.4 v1(10.66,34.66) ; U1.A1 45.42,42.93 20.62,42.93 PWRHLD.1 14.05,44.06 12.48,42.49 10.87,42.49 10.85,42.47 v1(10.67,42.47)
  TOP w0.254: R16.1 11.45,56.77 11.43,56.75 v1(10.82,56.75)
  INTERNAL3 w0.152: v1(10.82,56.75) 10.82,56.19 10.67,56.03 v1(10.67,42.47) 10.67,34.75 10.66,34.74 v1(10.66,34.66)
  INTERNAL3 w0.254: J4.2 v1(26.63,34.64)
  BOTTOM w0.254: v1(26.63,34.64) 11.28,34.64 11.27,34.66 v1(10.66,34.66)
